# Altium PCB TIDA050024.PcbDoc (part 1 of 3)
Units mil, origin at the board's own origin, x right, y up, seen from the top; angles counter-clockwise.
Board outline 5500.19 x 3301.39 mil, 4 copper layers (Top Layer, Signal Layer 1, Signal Layer 2, Bottom Layer), stack 46.8 mil thick; 153 components, 88 nets, 368 pads, 374 vias.
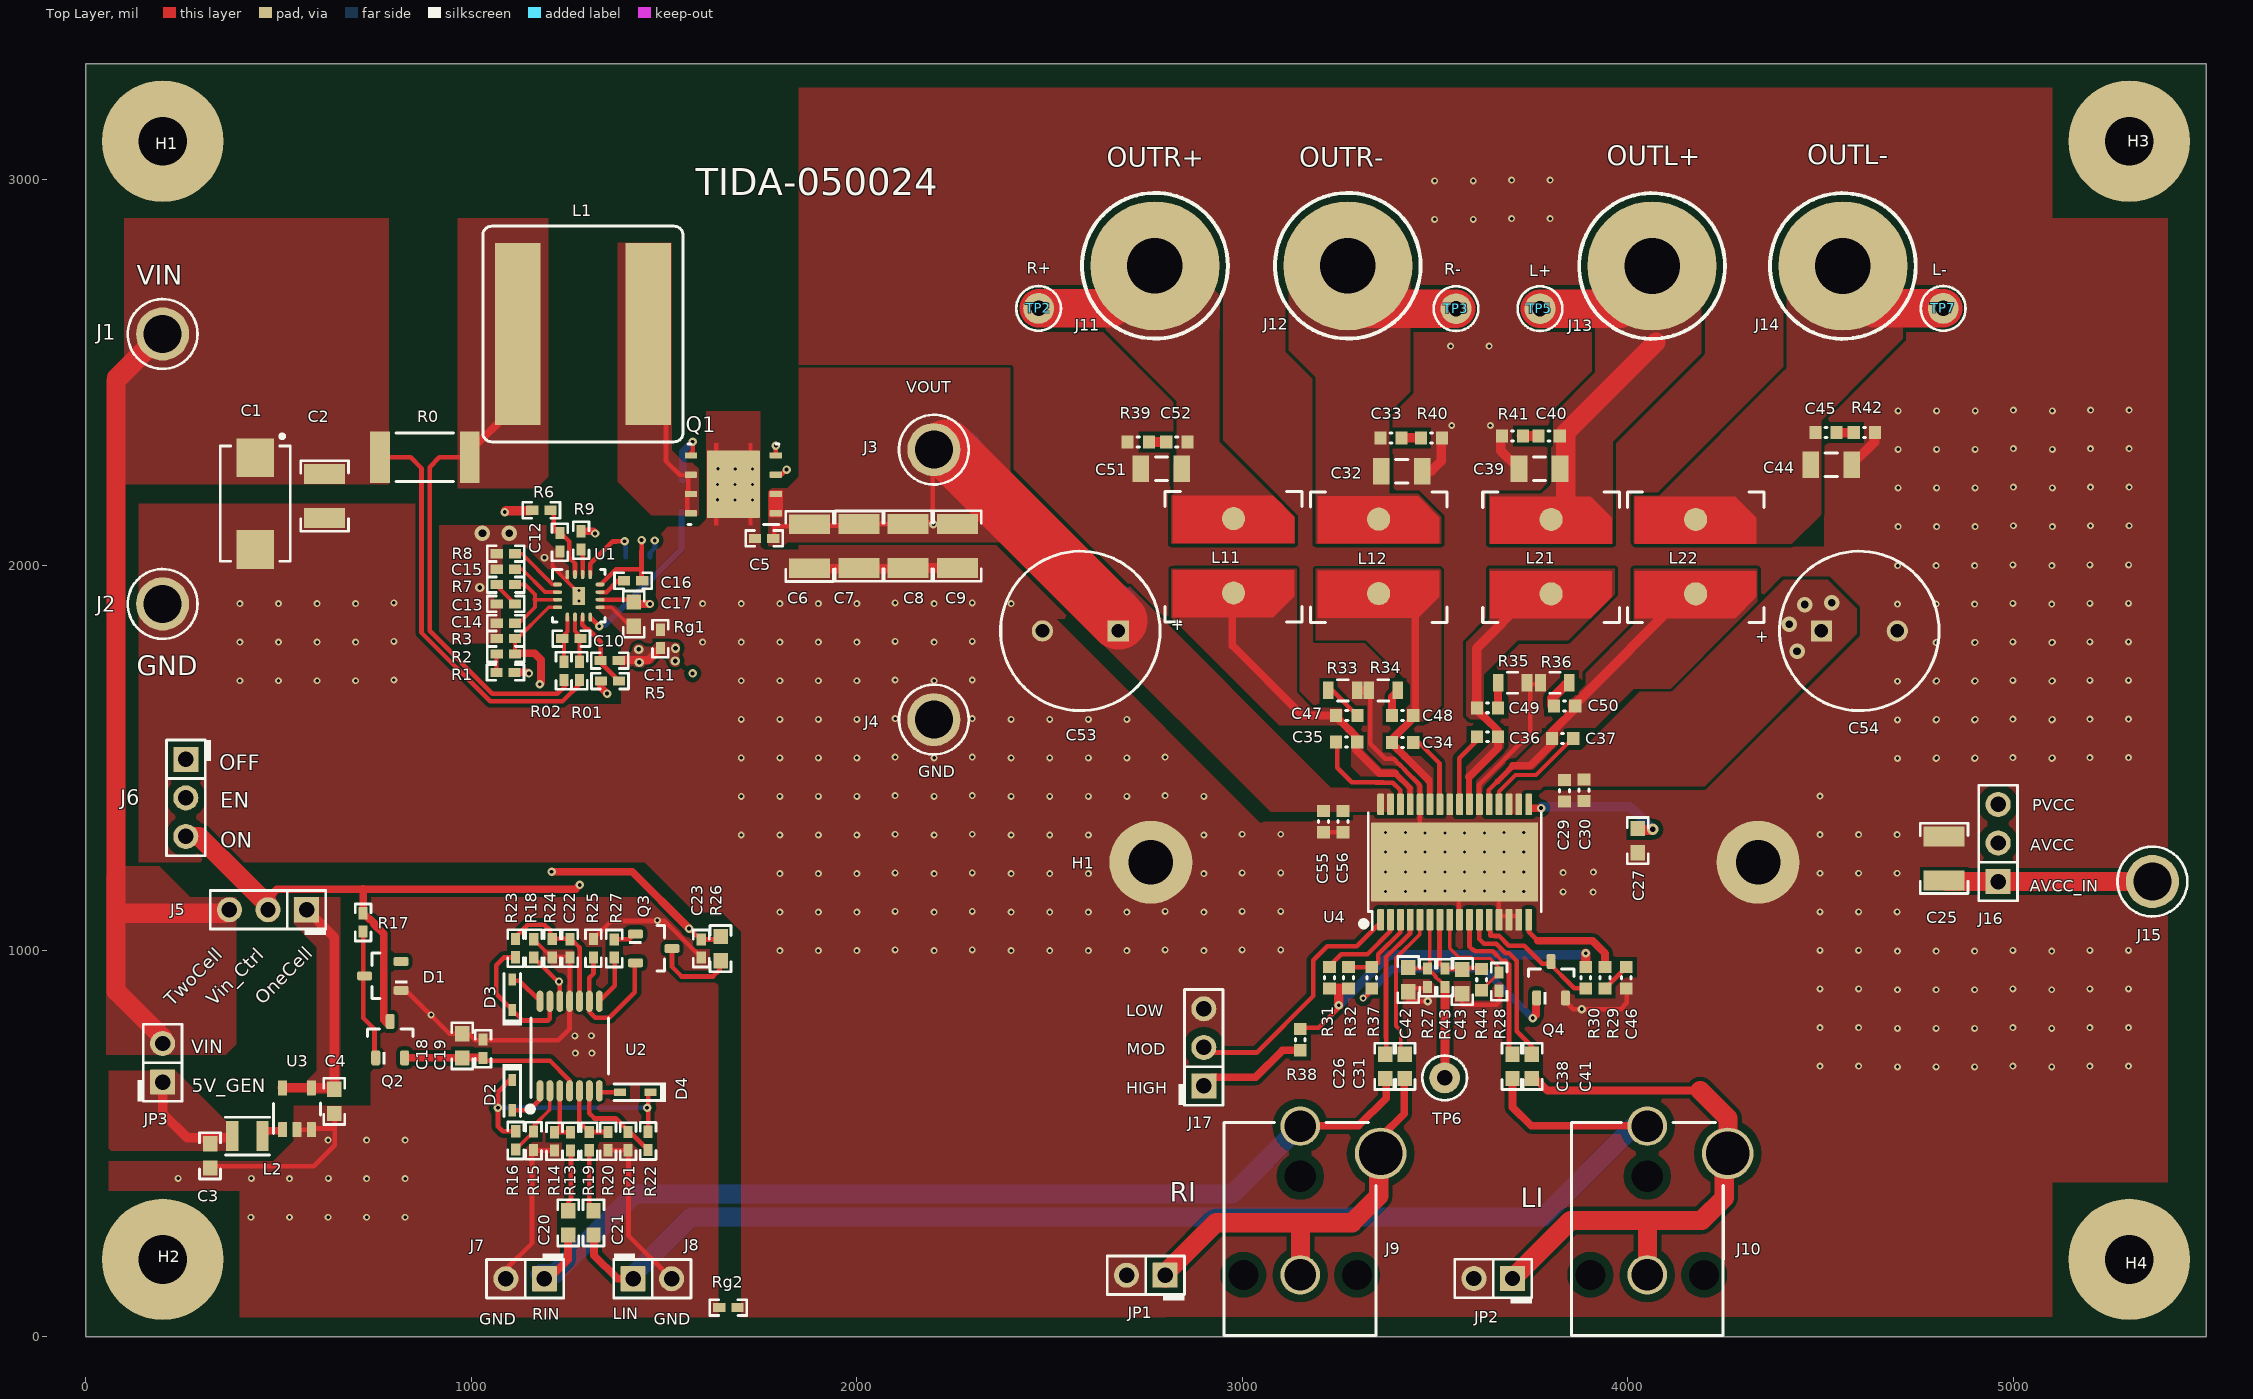
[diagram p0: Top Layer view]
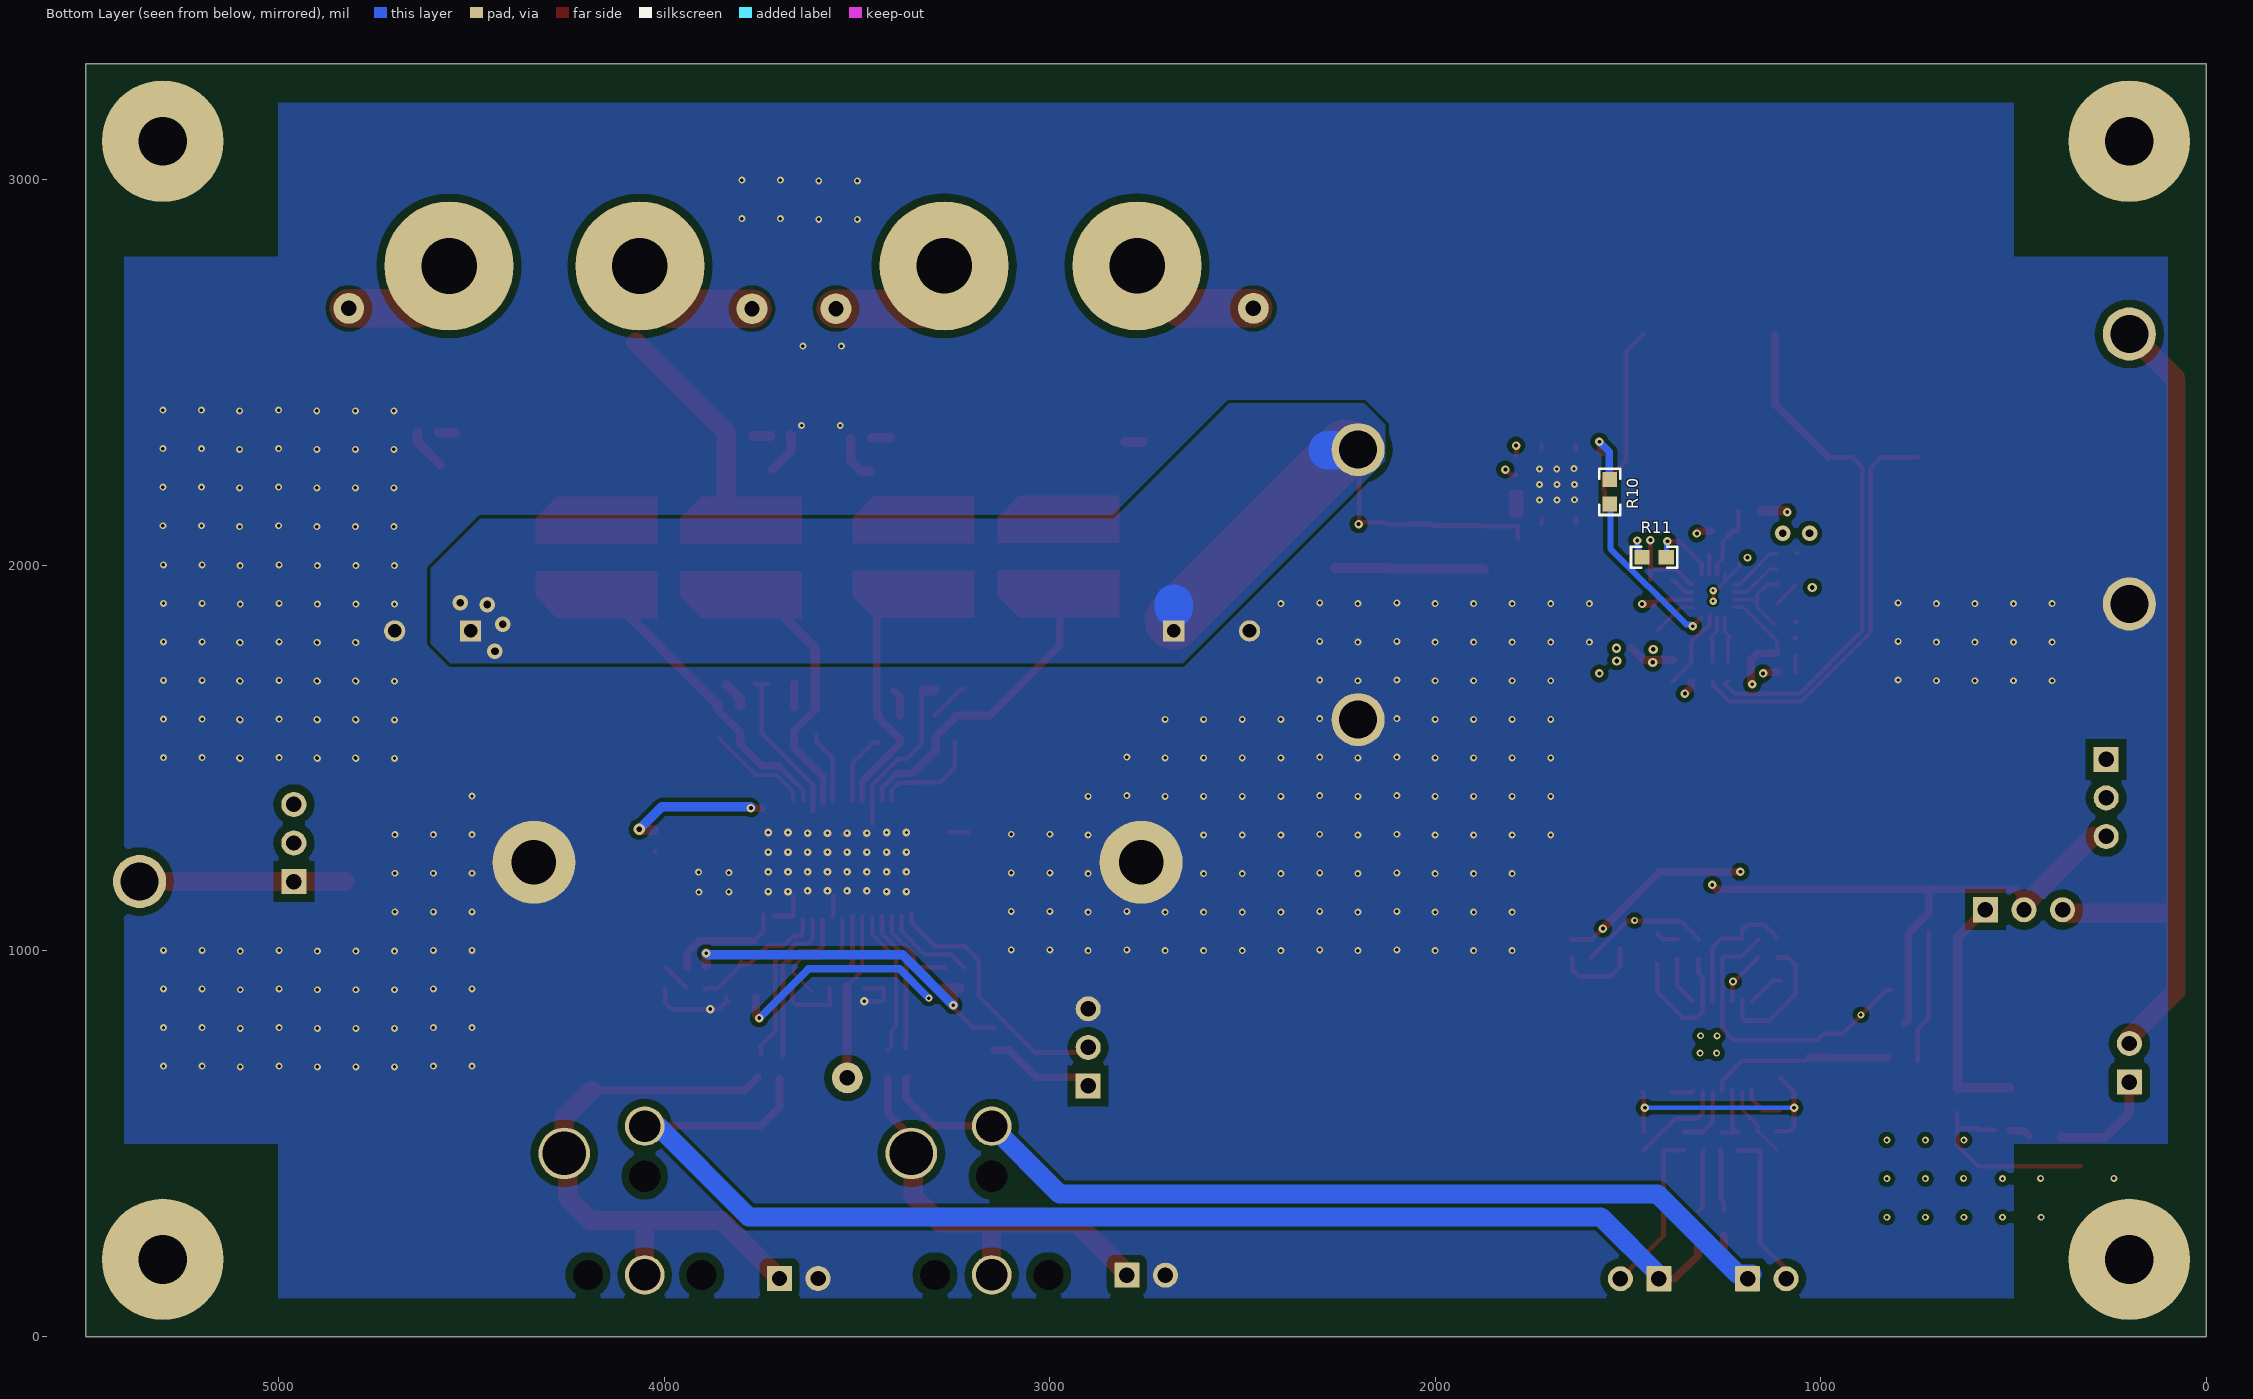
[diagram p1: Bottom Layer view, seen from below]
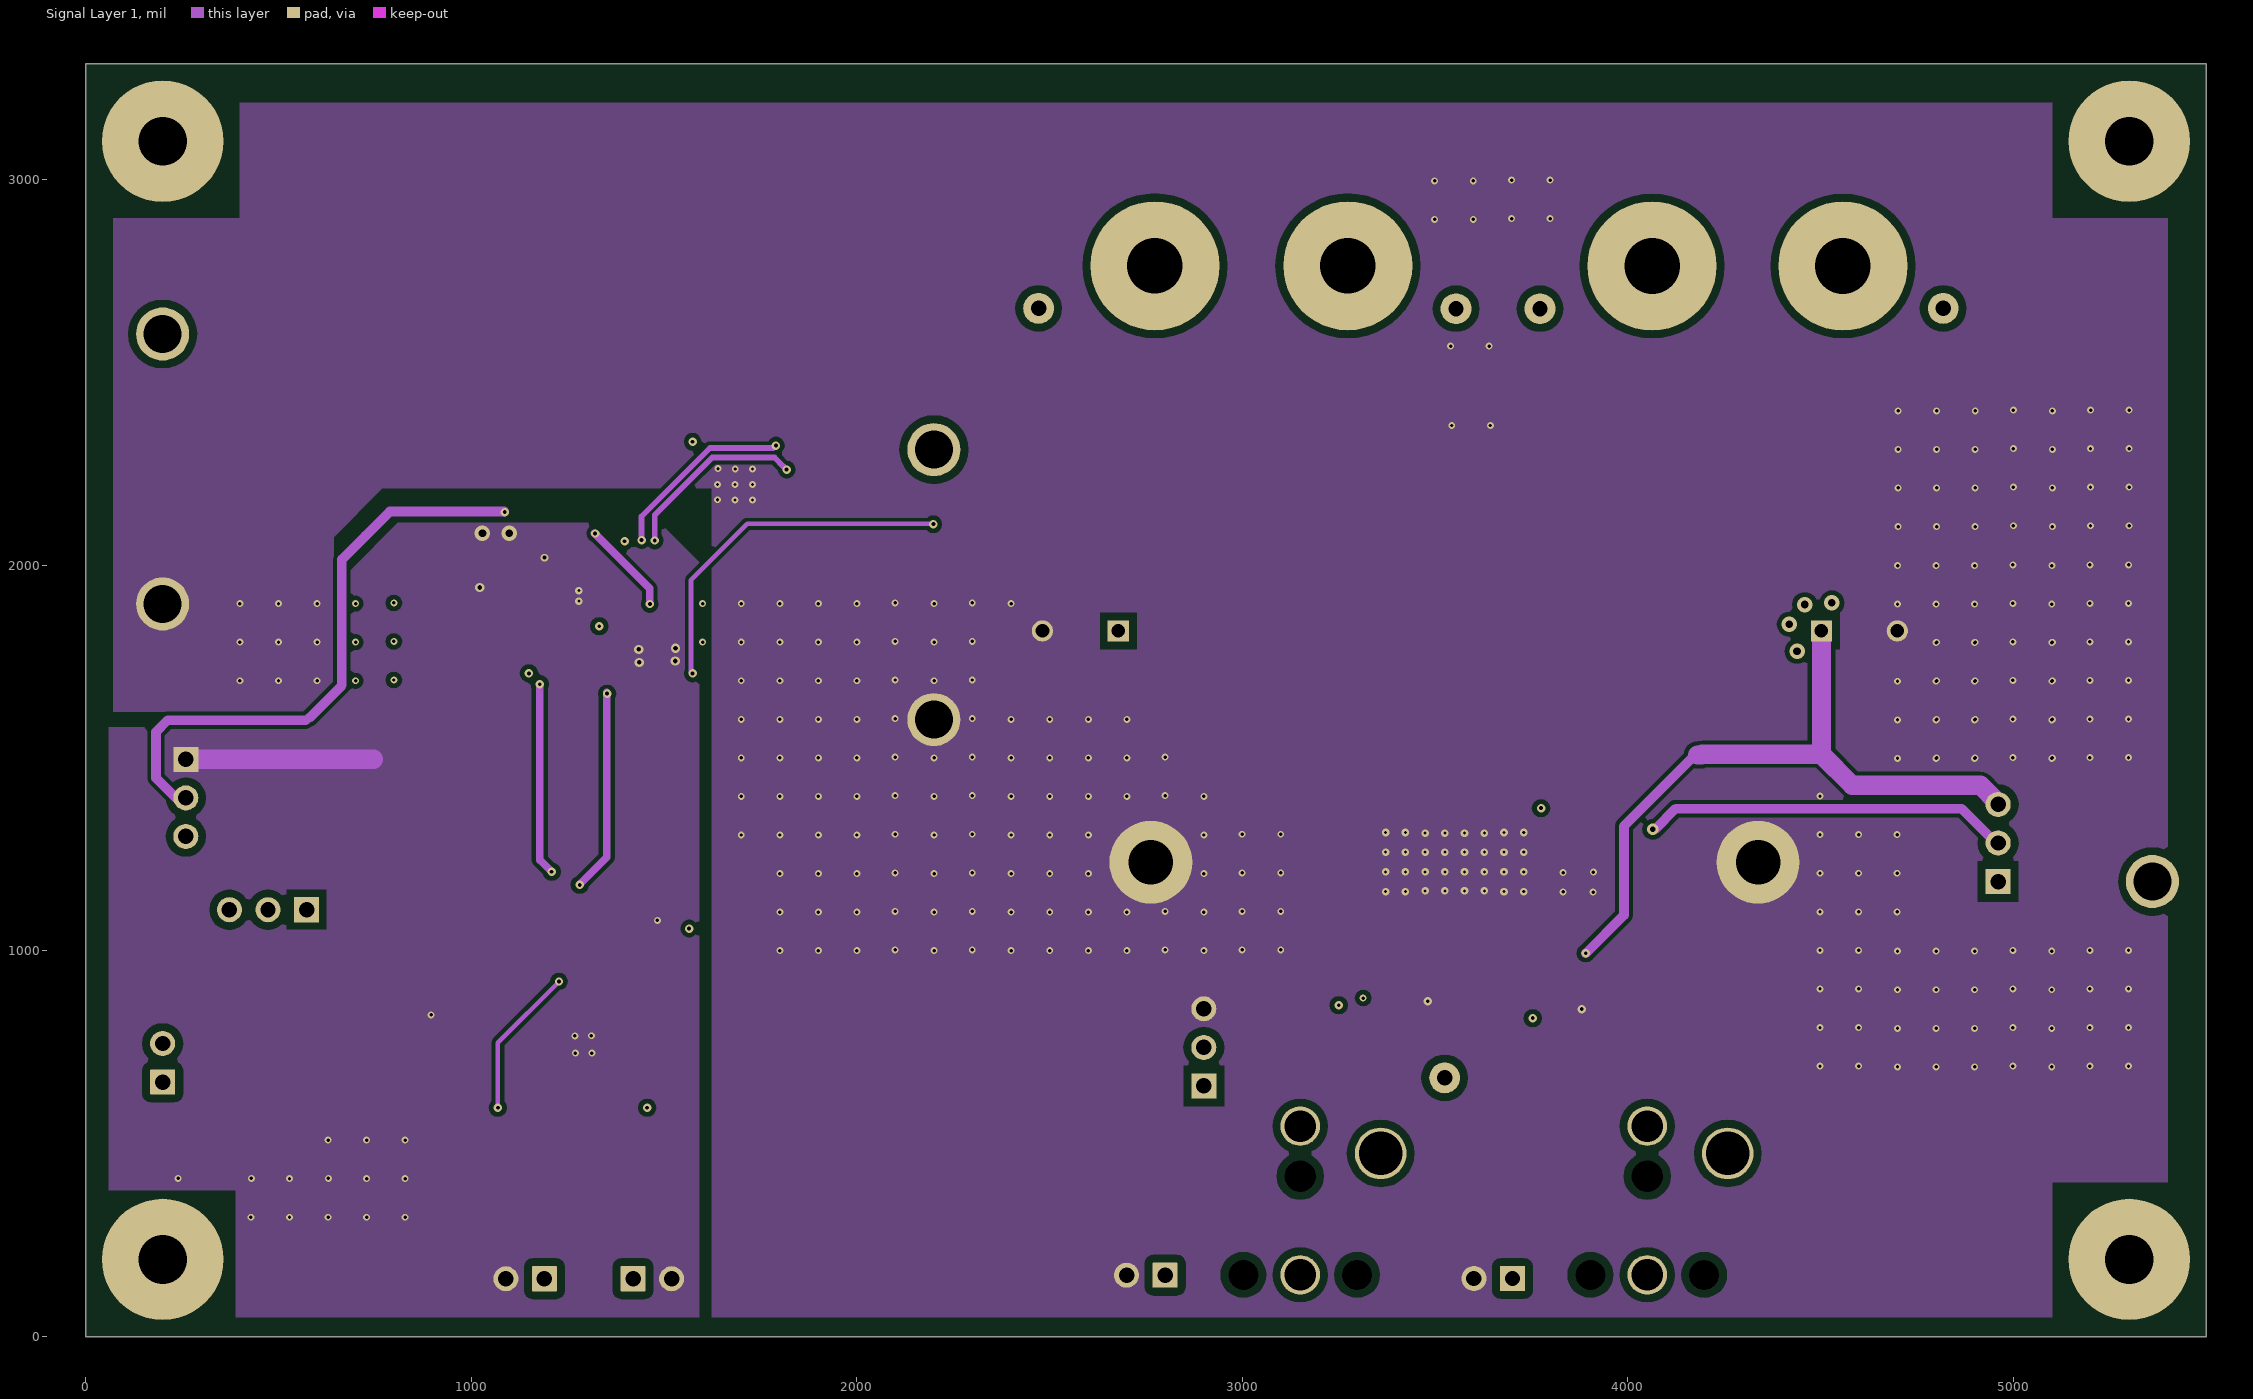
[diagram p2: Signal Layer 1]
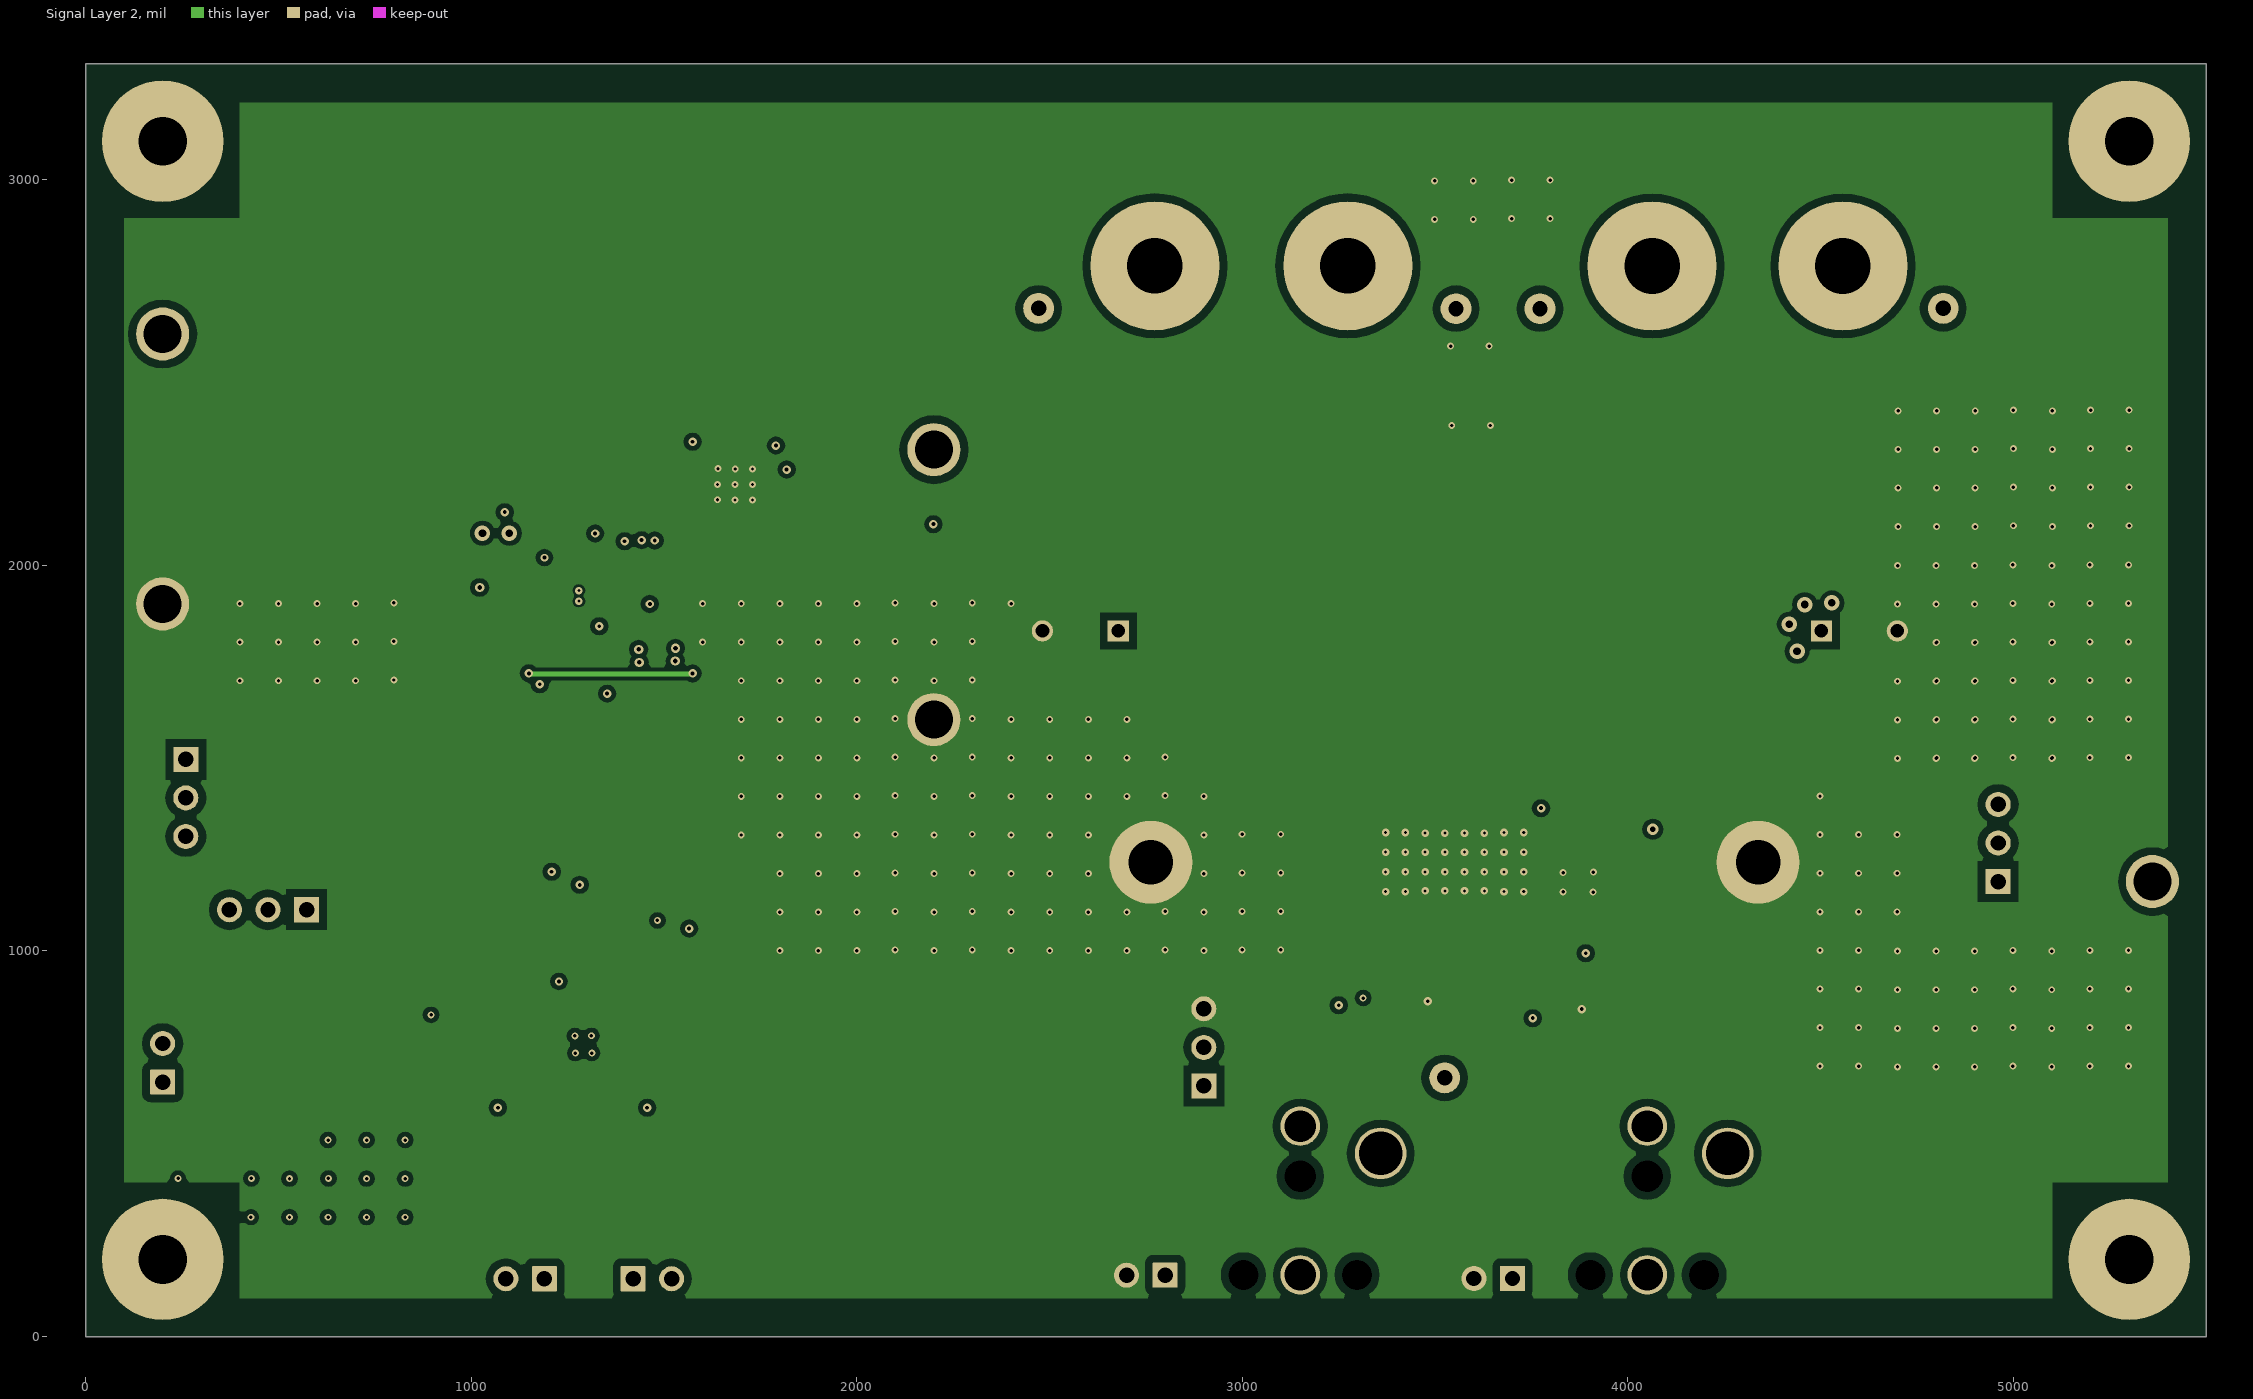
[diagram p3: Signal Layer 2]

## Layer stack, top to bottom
Top Solder: solder mask 0.4, Solder Resist, Dk 3.5
Top Layer: signal copper 2.8
Dielectric1: core 12.8, FR-4, Dk 4.2
Signal Layer 1: signal copper 1.4
Dielectric 3: core 12.8, Dk 4.2
Signal Layer 2: signal copper 1.4
Dielectric 2: core 12.8, Dk 4.2
Bottom Layer: signal copper 2.8
Bottom Solder: solder mask 0.4, Solder Resist, Dk 3.5

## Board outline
0,0 5500,0 5500.19,0.19 5500.19,3301.39 0.57,3301.39

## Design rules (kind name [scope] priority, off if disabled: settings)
AcuteAngle [All] p1: minimum=4.50000000000000E+0001 checktracksonly=FALSE
AssemblyTestPointUsage [All] p1: valid=2
Clearance "U1 Clearance" [InComponent('U1')] p1: gap=6 ignorepadtopadclearanceinfootprint=FALSE except(0: Arc-Hole Track-Hole SMDPad-Hole THPad-Hole Via-Hole Fill-Hole Poly-Hole Region-Hole Text-Hole)
Clearance "U2 Clearance" [InComponent('U2')] p2: gap=7.5 ignorepadtopadclearanceinfootprint=FALSE except(0: Arc-Hole Track-Hole SMDPad-Hole THPad-Hole Via-Hole Fill-Hole Poly-Hole Region-Hole Text-Hole; 7: Arc-Text)
Clearance "U3 Clearance" [InComponent('U3')] p3: gap=7.5 ignorepadtopadclearanceinfootprint=FALSE except(0: Arc-Hole Track-Hole SMDPad-Hole THPad-Hole Via-Hole Fill-Hole Poly-Hole Region-Hole Text-Hole; 7: Arc-Text)
Clearance Clearance_BoardEdge [OnCopper and Not InComponentClass('Logo') and not InComponentClass('FiducialMark') and not InRegion(1000,500,4000,800) vs IsKeepOut] p4: gap=15 ignorepadtopadclearanceinfootprint=FALSE except(0: Arc-Hole Track-Region Track-Hole SMDPad-Hole THPad-Hole Via-Hole Fill-Hole Poly-Hole Region-Hole Text-Hole; 10: Track-Poly Poly-Poly Poly-Region Poly-Text Region-Region Region-Text; 30: Arc-Arc Text-Text)
Clearance [All] p5: gap=8 ignorepadtopadclearanceinfootprint=FALSE except(0: Arc-Hole Track-Hole SMDPad-Hole THPad-Hole Via-Hole Fill-Hole Poly-Hole Region-Hole Text-Hole; 6: Track-Track Track-SMDPad SMDPad-SMDPad SMDPad-THPad; 10: Track-Poly SMDPad-Poly; 12: Via-Poly; 20: THPad-Poly)
ComponentClearance ComponentClearance_MountingHoles_FiducialMarks [InComponentClass('Mounting Holes') vs InComponentClass('FiducialMark')] p1: gap=20 collisioncheckmode=3 verticalgap=10 showdistances=FALSE
ComponentClearance ComponentClearance_SHUNT [InComponentClass('Shunt')] p2: gap=0 collisioncheckmode=3 verticalgap=0 showdistances=FALSE
ComponentClearance ComponentClearance_Logo [All] p3: gap=10 collisioncheckmode=3 verticalgap=10 showdistances=FALSE
ComponentClearance ComponentClearance_ScrewToNut [(HasFootprint('NY PMS 440 0025 PH')) vs (HasFootprint('Keystone_1902C'))] p4: gap=5 collisioncheckmode=3 verticalgap=10 showdistances=FALSE
ComponentClearance ComponentClearance_MountingHoles [InComponentClass('Mounting Holes')] p5: gap=250 collisioncheckmode=3 verticalgap=100000 showdistances=FALSE
ComponentClearance ComponentClearance_SmallPassives [HasFootprint('0201*') or HasFootprint('0402*') or HasFootprint('0508') or HasFootprint('0603*') or HasFootprint('0612') or HasFootprint('0805*') or HasFootprint('0815*') or HasFootprint('0830*') or HasFootprint('1206*') or HasFootprint('1210*') or HasFootprint('1808*') or HasFootprint('1812*') or HasFootprint('1825*') or HasFootprint('2010*') or HasFootprint('2220*') or HasFootprint('2225*') or HasFootprint('2512*') or HasFootprint('2728*') or HasFootprint('3518*') vs HasFootprint('0201*') or HasFootprint('0402*') or HasFootprint('0508') or HasFootprint('0603*') or HasFootprint('0612') or HasFootprint('0805*') or HasFootprint('0815*') or HasFootprint('0830*') or HasFootprint('1206*') or HasFootprint('1210*') or HasFootprint('1808*') or HasFootprint('1812*') or HasFootprint('1825*') or HasFootprint('2010*') or HasFootprint('2220*') or HasFootprint('2225*') or HasFootprint('2512*') or HasFootprint('2728*') or HasFootprint('3518*')] p6: gap=20 collisioncheckmode=3 verticalgap=10 showdistances=FALSE
ComponentClearance ComponentClearance_THtoSMT [IsThruComponent vs IsSMTComponent] p7 off: gap=10 collisioncheckmode=3 verticalgap=100000 showdistances=FALSE
ComponentClearance ComponentClearance_THtoTH [IsThruComponent vs IsThruComponent] p8: gap=10.11 collisioncheckmode=3 verticalgap=100000 showdistances=FALSE
ComponentClearance [All] p9: gap=10 collisioncheckmode=3 verticalgap=10 showdistances=FALSE
DiffPairsRouting [All] p1: maxlimit=100 minlimit=10 mostfreqgap=10 toplayer_minwidth=15 toplayer_maxwidth=15 toplayer_prefwidth=15 midlayer1_minwidth=15 midlayer1_maxwidth=15 midlayer1_prefwidth=15 midlayer2_minwidth=15 midlayer2_maxwidth=15 midlayer2_prefwidth=15 bottomlayer_minwidth=15 bottomlayer_maxwidth=15 bottomlayer_prefwidth=15 maxuncoupledlength=1000
FabricationTestPointUsage TestPointUsage [All] p1: valid=2 allowmultiple=FALSE
FabricationTestpoint Testpoint [All] p1: side=3 testpointundercomponent=TRUE minsize=40 maxsize=100 preferedsize=60 minholesize=0 maxholesize=40 preferedholesize=32 testpointgrid=1 allowsidetop=TRUE allowsidebottom=TRUE usegrid=TRUE gridtolerance=0.01
FanoutControl Fanout_LCC [IsLCC] p1: bgadir=Out bgaviamode=Centered fanoutstyle=Auto fanoutdirection=Alternating viagrid=1 // Fanout_LCC (Default Rule)
FanoutControl Fanout_BGA [IsBGA] p2: bgadir=Out bgaviamode=Centered fanoutstyle=Auto fanoutdirection=Alternating viagrid=1 // Fanout_BGA (Default Rule)
FanoutControl Fanout_Default [All] p4: bgadir=Out bgaviamode=Centered fanoutstyle=Auto fanoutdirection=Alternating viagrid=1 // Fanout_Default (Default Rule)
FanoutControl Fanout_Small [(CompPinCount < 5)] p5: bgadir=Out bgaviamode=Centered fanoutstyle=Auto fanoutdirection=OutThenIn viagrid=1 // Fanout_Small (Default Rule)
HoleSize [All] p1: absolutevalues=TRUE maxlimit=100 minlimit=8 maxpercent=80.000 minpercent=20.000
HoleToHoleClearance [All] p1: gap=1 allowstackedmicrovias=TRUE
MinimumAnnularRing MinimumAnnularRing_small [TouchesRoom('BGA_Room')] p1: minimumring=2.8
MinimumAnnularRing MinimumAnnularRing_ThermalPadVias [IsVia and InAnyComponent] p2: minimumring=5.91
MinimumAnnularRing [All] p3: minimumring=5
MinimumSolderMaskSliver MinimumSolderMaskSliver_Logo [InComponentClass('Logo') vs InComponentClass('Logo')] p1: minsoldermaskwidth=0.7
MinimumSolderMaskSliver [All] p2: minsoldermaskwidth=3
PlaneClearance [All] p1: clearance=10
PlaneConnect [All] p1: planeconnectstyle=Direct reliefexpansion=10 reliefentries=4 reliefconductorwidth=10 reliefairgap=10
PolygonConnect PolygonConnect-TH-Relief [IsPoly vs (IsThruPin)  And Not (InComponent('U3'))  And Not (InComponent('U4'))] p1: connectstyle=Direct reliefconductorwidth=20 reliefentries=4 polygonreliefangle="90 Angle" airgapwidth=10
PolygonConnect PolygonConnect-DirectConn [All] p2: connectstyle=Direct reliefconductorwidth=10 reliefentries=4 polygonreliefangle="90 Angle" airgapwidth=10
PolygonConnect [All] p3: connectstyle=Relief reliefconductorwidth=10 reliefentries=4 polygonreliefangle="90 Angle" airgapwidth=10
RoutingVias ThermalPadVias [IsVia and InAnyComponent] p1: holewidth=7.87 width=19.68 viastyle="Through Hole" minholewidth=7.87 minwidth=19.68 maxholewidth=12.99 maxwidth=23.62
RoutingVias [All] p2: holewidth=10 width=22 viastyle="Through Hole" minholewidth=4 minwidth=10 maxholewidth=100 maxwidth=100
SMDToCorner [All] p1: distance=0
SilkToBoardRegionClearance [Not ((IsComment or IsDesignator) And (Hide <> 'False')) and not InRegion(1000,500,4000,800)] p1:
SilkToSilkClearance SilkToSilkClearance_Pb-FreeLogo [(HasFootprint('Pb-Free_Overlay_Medium') OR HasFootprint('Pb-Free_Overlay_Small')) vs (HasFootprint('Pb-Free_Overlay_Medium') OR HasFootprint('Pb-Free_Overlay_Small'))] p1: silktosilkclearance=0
SilkToSilkClearance [All] p2: silktosilkclearance=3
SilkToSolderMaskClearance SilkToComonentPadClearance [IsPad and InAnycomponent] p1 off: minsilkscreentomaskgap=5 clearancetoexposedcopper=TRUE
SilkToSolderMaskClearance "Silk to Solder Mask Opening" [All] p2 off: minsilkscreentomaskgap=4 clearancetoexposedcopper=TRUE
SolderMaskExpansion [All] p1: expansion=1
Width [All] p1: maxlimit=100 minlimit=6 preferedwidth=10 checkconnectedcopper=TRUE
13 further rules are at their usual default settings.

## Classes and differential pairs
component class "Mounting Holes": H1 H2 H3 H4
component class AssemblyNote: ZZ1 ZZ2 ZZ3
component class TIDA050024_Hardware: H1 H2 H3 H4 ZZ1 ZZ2 ZZ3
component class TIDA050024_1: C1 C2 C3 C4 C5 C6 C7 C8 C9 C10 C11 C12 C13 C14 C15 C16 C17 C18 C19 C20 C21 C22 C23 D1 D2 D3 D4 J1 J2 J3 J4 J5 J6 J7 J8 JP3 L1 L2 Q1 Q2 Q3 R0 R1 R01 R02 R2 R3 R5 R6 R7 R8 R9 R10 R11 R12 R13 R14 R15 R16 R17 R18 R19 R20 R21 R22 R23 R24 R25 R26 R27 Rg1 Rg2 U1 U2 U3
component class Header: J5 J6 J7 J8 J16 J17 JP1 JP2 JP3
component class "Full Flood": C29 C30 C34 C35 C36 C37 C55 C56 R33 R34 R35 R36
component class "LC Caps": C32 C39 C44 C51
component class TIDA050024_2: C25 C26 C27 C29 C30 C31 C32 C33 C34 C35 C36 C37 C38 C39 C40 C41 C42 C43 C44 C45 C46 C47 C48 C49 C50 C51 C52 C53 C54 C55 C56 H1 J9 J10 J11 J12 J13 J14 J15 J16 J17 JP1 JP2 L11 L12 L21 L22 Q4 R27 R28 R29 R30 R31 R32 R33 R34 R35 R36 R37 R38 R39 R40 R41 R42 R43 R44 TP2 TP3 TP5 TP6 TP7 U4

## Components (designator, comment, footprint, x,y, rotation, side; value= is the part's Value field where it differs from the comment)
C1 "T495D476M025ATE120" 7343-31 440,2160 r270 top value=47uF
C2 "GRM32ER61E226KE15L" 1210_270 620,2180 r270 top value=22uF
C3 "GRM188R61E106MA73D" 0603 322.91,468.45 r270 top value=10uF
C4 "GRM188R61E106MA73D" 0603 645,610 r270 top value=10uF
C5 "C1005X5R1E105K050BC" 0402 1760,2070 r180 top value=1uF
C6 "GRM32ER61E226KE15L" 1210_270 1877.87,2049.47 r270 top value=22uF
C7 "GRM32ER61E226KE15L" 1210_270 2005.85,2049.96 r270 top value=22uF
C8 "GRM32ER61E226KE15L" 1210_270 2133.02,2050.19 r270 top value=22uF
C9 "GRM32ER61E226KE15L" 1210_270 2260.76,2050.18 r270 top value=22uF
C10 "GRM1555C1H101JA01D" 0402 1260,1810 r0 top value=100pF
C11 "CGA2B3X7R1H104K050BB" 0402 1359.34,1752.85 r0 top value=0.1uF
C12 "CGA2B3X7R1H104K050BB" 0402 1230,2060 r270 top value=0.1uF
C13 "GCM155R71E223KA55D" 0402 1090,1900 r180 top value=0.022uF
C14 "GRM1555C1H101JA01D" 0402 1090,1850 r180 top value=100pF
C15 "CGA2B3X7R1H104K050BB" 0402 1090,1990 r180 top value=0.1uF
C16 "CGA2B3X7R1H104K050BB" 0402 1420,1960 r180 top value=0.1uF
C17 "GRM188R61E106MA73D" 0603 1421.37,1873.58 r270 top value=10uF
C18 "GRM188R61E106MA73D" 0603 976.99,754.04 r90 top value=10uF
C19 "CGA2B3X7R1H104K050BB" 0402 1031,746.41 r90 top value=0.1uF
C20 "GRM188R61E106MA73D" 0603 1251.93,295.02 r90 top value=10uF
C21 "GRM188R61E106MA73D" 0603 1317.29,294.67 r90 top value=10uF
C22 "C1005X5R1E105K050BC" 0402 1256.12,1006.77 r270 top value=1uF
C23 "GRM1555C1H101JA01D" 0402 1596.87,1006.26 r270 top value=100pF
C25 "GRM32ER61E226KE15L" 1210_270 4820,1240 r90 top value=22uF
C26 "GRM188R61E105KA12D" 0603 3370.57,700.57 r90 top value=1uF
C27 "GRM188R61E105KA12D" 0603 4025.43,1286.03 r270 top value=1uF
C29 "GCM188R71H104KA57D" 0603L 3835.57,1415.57 r90 top value=0.1uF
C30 "GRM1885C1H102JA01D" 0603L 3886.18,1416.92 r90 top value=1000pF
C31 "GRM188R61E105KA12D" 0603 3420.57,700.57 r90 top value=1uF
C32 "GRM31MR71H684KA88L" 1206L 3413.43,2244.29 r0 top value=0.68uF
C33 "GRM188R71H103KA01D" 0603L 3385.57,2330.57 r0 top value=0.01uF
C34 "GCM188R71H104KA57D" 0603L 3415.57,1540.57 r0 top value=0.1uF
C35 "GCM188R71H104KA57D" 0603L 3270.23,1542.04 r180 top value=0.1uF
C36 "GCM188R71H104KA57D" 0603L 3635.57,1555.57 r180 top value=0.1uF
C37 "GCM188R71H104KA57D" 0603L 3830.57,1550.57 r0 top value=0.1uF
C38 "GRM188R61E105KA12D" 0603 3700.57,700.57 r90 top value=1uF
C39 "GRM31MR71H684KA88L" 1206L 3770.57,2250.57 r180 top value=0.68uF
C40 "GRM188R71H103KA01D" 0603L 3795.57,2335.57 r180 top value=0.01uF
C41 "GRM188R61E105KA12D" 0603 3750.57,700.57 r90 top value=1uF
C42 "GRM188R61E105KA12D" 0603 3430.57,925.57 r90 top value=1uF
C43 "GRM188R61E105KA12D" 0603 3570.57,920.57 r90 top value=1uF
C44 "GRM31MR71H684KA88L" 1206L 4527.15,2260.95 r0 top value=0.68uF
C45 "GRM188R71H103KA01D" 0603L 4513.48,2344.34 r0 top value=0.01uF
C46 "GRM1885C1H470JA01D" 0603L 3995.57,930.57 r270 top value=47pF
C47 "GRM1885C1H331JA01D" 0603L 3270.57,1610.57 r180 top value=330pF
C48 "GRM1885C1H331JA01D" 0603L 3415.57,1610.57 r0 top value=330pF
C49 "GRM1885C1H331JA01D" 0603L 3635.57,1630.57 r180 top value=330pF
C50 "GRM1885C1H331JA01D" 0603L 3835.57,1635.57 r0 top value=330pF
C51 "GRM31MR71H684KA88L" 1206L 2790,2250 r180 top value=0.68uF
C52 "GRM188R71H103KA01D" 0603L 2830,2320 r180 top value=0.01uF
C53 "EEU-FC1V221" FC_1000x1250 2580,1830 r180 top value=220uF
C54 "EEU-FC1V221" FC_1000x1250 4600,1830 r0 top value=220uF
C55 "GCM188R71H104KA57D" 0603L 3210.57,1335.57 r90 top value=0.1uF
C56 "GRM1885C1H102JA01D" 0603L 3260.57,1335.57 r90 top value=1000pF
D1 "BZX84C4V3LT1G" SOT-23 770.87,935.34 r180 top value=4.3V
D2 "1N4148WT" Fairchild_SOD-523F 1106.87,626.26 r270 top value=75V
D3 "1N4148WT" Fairchild_SOD-523F 1106.87,886.26 r90 top value=75V
D4 "1N4148WT" Fairchild_SOD-523F 1425.49,633.82 r180 top value=75V
H1 "NY PMS 440 0025 PH" "NY PMS 440 0025 PH" 200,3100 r90 top
H1 "ATS-TI10P-521-C1-R1" HSINK_ATS-TI10P-521-C1-R1 3550,1230 r180 top locked
H2 "NY PMS 440 0025 PH" "NY PMS 440 0025 PH" 200,200 r90 top
H3 "NY PMS 440 0025 PH" "NY PMS 440 0025 PH" 5300,3100 r90 top
H4 "NY PMS 440 0025 PH" "NY PMS 440 0025 PH" 5300,200 r90 top
J1 "1502-2" Keystone1502-2 200,2600 r0 top
J2 "1502-2" Keystone1502-2 200,1900 r0 top
J3 "1502-2" Keystone1502-2 2200,2300 r0 top
J4 "1502-2" Keystone1502-2 2200,1600 r0 top
J5 "TSW-103-07-G-S" TSW-103-07-G-S 473.18,1106.94 r180 top
J6 "TSW-103-07-G-S" TSW-103-07-G-S 260.09,1397.08 r270 top
J7 "TSW-102-07-G-S" TSW-102-07-G-S 1140,150 r180 top
J8 "TSW-102-07-G-S" TSW-102-07-G-S 1470,150 r0 top
J9 "RIN" Keystone_971 3150,160 r90 top
J10 "LIN" Keystone_970 4050,160 r90 top
J11 "ROUT+" Keystone_7006 2773.39,2776.89 r0 top
J12 "ROUT-" Keystone_7007 3273.39,2776.89 r0 top
J13 "LOUT+" Keystone_7006 4062.44,2776.3 r0 top
J14 "LOUT-" Keystone_7007 4557.44,2776.3 r0 top
J15 "Suggest using a net name here" Keystone1502-2 5360,1180 r0 top value=Double
J16 "AVCC-SEL" PBC03SAAN 4960,1280 r90 top
J17 "TSW-103-07-G-S" TSW-103-07-G-S 2900,750 r90 top
JP1 "TSW-102-07-G-S" TSW-102-07-G-S 2749.79,159.14 r180 top
JP2 "TSW-102-07-G-S" TSW-102-07-G-S 3650.57,150.57 r180 top
JP3 "TSW-102-07-G-S" TSW-102-07-G-S 200,710 r90 top
L1 "XAL1350-302MEB" XAL1350 1290,2600 r0 top value=3uH
L2 "DFE252012F-2R2M=P2" DFE252012C 420,520 r0 top value=2.2uH
L11 "SRT8045-103MEB" SRT8045 2977.09,2022.82 r90 top value=10uH
L12 "SRT8045-103MEB" SRT8045 3353.47,2021.36 r90 top value=10uH
L21 "SRT8045-103MEB" SRT8045 3800.57,2020.57 r90 top value=10uH
L22 "SRT8045-103MEB" SRT8045 4175.57,2020.57 r90 top value=10uH
Q1 "CSD87351Q5D" DQY0008A 1680,2210 r180 top value=30V
Q2 "BC850CLT1G" SOT-23 790,770 r90 top value="45 V"
Q3 "BSS138" SOT-23 1473.54,1006.62 r0 top value=50V
Q4 "BC850CLT1G" SOT-23 3800.57,925.57 r90 top value="45 V"
R0 "CSNL2512FT2L00" 2512 880,2280 r0 top value=0.002
R01 "CRCW040210R0FKED" 0402 1280.56,1726.59 r270 top value=10.0
R1 "CRCW040249R9FKED" 0402 1089.01,1722.61 r0 top value=49.9
R02 "CRCW040210R0FKED" 0402 1240.56,1726.59 r270 top value=10.0
R2 "ERJ-2RKF2003X" 0402 1090,1770 r180 top value=200k
R3 "CRCW040256K2FKED" 0402 1090,1810 r0 top value=56.2k
R5 "CRCW040210R0FKED" 0402 1360,1700 r180 top value=10.0
R6 "CRCW040210R0FKED" 0402 1182.18,2142.81 r180 top value=10.0
R7 "CRCW04027K50FKED" 0402 1090,1950 r0 top value=7.50k
R8 "CRCW0402137KFKED" 0402 1090,2030 r0 top value=137k
R9 "CRCW0402100KFKED" 0402 1285,2065 r270 top value=100k
R10 "RCS06030000Z0EA" 0603 1547.78,2190.77 r90 bottom value=0
R11 "RCS06030000Z0EA" 0603 1432.37,2021.02 r0 bottom value=0
R13 "CRCW04020000Z0ED" 0402 1257.9,506.32 r270 top value=0
R14 "CRCW0402100KDHEDP" 0402 1215.81,506.32 r90 top value=100k
R15 "CRCW040210K2FKED" 0402 1162.1,507.78 r90 top value=10.2k
R16 "CRCW040210K2FKED" 0402 1115.71,508.72 r90 top value=10.2k
R17 "CRCW04023K01FKED" 0402 720.03,1074.02 r90 top value=3.01k
R18 "CRCW0402100KDHEDP" 0402 1162.44,1006.77 r270 top value=100k
R19 "CRCW04020000Z0ED" 0402 1306.42,506.7 r270 top value=0
R20 "CRCW0402100KDHEDP" 0402 1355.33,506.82 r90 top value=100k
R21 "CRCW040210K2FKED" 0402 1407.1,506.82 r90 top value=10.2k
R22 "CRCW040210K2FKED" 0402 1459.04,507.43 r90 top value=10.2k
R23 "CRCW040212R1FKED" 0402 1115.13,1007.4 r90 top value=12.1
R24 "ERJ-2RKF1004X" 0402 1210.39,1007.09 r90 top value=1.00Meg
R25 "CRCW040218K7FKED" 0402 1317.3,1006.97 r270 top value=18.7k
R26 "CRCW060310K5FKEA" 0603 1646.87,1006.26 r90 top value=10.5k
R27 "CRCW04020000Z0ED" 0402 1371.04,1006.51 r270 top value=0
R27 "CRCW040220K5FKED" 0402 3480.57,930.57 r90 top value=20.5k
R28 "CRCW040239K0JNED" 0402 3665.57,920.57 r90 top value=39k
R29 "RG1608P-472-B-T5" 0603L 3940.57,930.57 r90 top value=4.70k
R30 "RC0603FR-07100KL" 0603L 3890.57,930.57 r270 top value=100k
R31 "RC0603FR-07499KL" 0603L 3225.57,930.57 r270 top value=499k
R32 "RC0603FR-07100KL" 0603L 3275.57,930.57 r90 top value=100k
R33 "CRCW080510R0JNEA" 0805_KTR 3260.57,1675.57 r180 top value=10
R34 "CRCW080510R0JNEA" 0805_KTR 3365.57,1675.57 r0 top value=10
R35 "CRCW080510R0JNEA" 0805_KTR 3700.57,1695.57 r180 top value=10
R36 "CRCW080510R0JNEA" 0805_KTR 3810.57,1695.57 r0 top value=10
R37 "RC0603FR-07100KL" 0603L 3335.57,930.57 r270 top value=100k
R38 "RC0603FR-07100KL" 0603L 3150,770 r90 top value=100k
R39 "CRCW06033R30JNEA" 0603L 2730,2320 r0 top value=3.3
R40 "CRCW06033R30JNEA" 0603L 3490.57,2330.57 r180 top value=3.3
R41 "CRCW06033R30JNEA" 0603L 3700.57,2335.57 r0 top value=3.3
R42 "CRCW06033R30JNEA" 0603L 4613.14,2344.93 r180 top value=3.3
R43 "ERJ-2GE0R00X" 0402 3525.57,930.57 r90 top value=0
R44 "RC0603FR-07100KL" 0603L 3620.57,925.57 r270 top value=100k
Rg1 "CRCW04020000Z0ED" 0402 1490.91,1809.42 r90 top value=0
Rg2 "CRCW04020000Z0ED" 0402 1666.88,75.17 r0 top value=0
TP2 "R+" Keystone5003 2471.45,2666.3 r0 top value=Orange
TP3 "R-" Keystone5003 3554.07,2665.65 r0 top value=Orange
TP5 "L+" Keystone5003 3771.82,2665.65 r0 top value=Orange
TP6 "PLIMIT" Keystone5003 3524.6,670.85 r0 top value=Orange
TP7 "L-" Keystone5003 4817.44,2666.3 r0 top value=Orange
U1 "TPS43061RTER" RTE0016E 1279.16,1920.84 r0 top
U2 "OPA4377AIPW" PW0014A_N 1255.49,753.47 r90 top
U3 "TPS613222ADBVR" DBV0005A_N 548.26,590.78 r90 top
U4 "TPA3128D2DAPR" DAP0032A_N 3550.57,1230.57 r90 top locked
ZZ1 "These assemblies are ESD sensitive, ESD precautions shall be observed." AssemblyNote 185,3938 r0 top
ZZ2 "These assemblies must be clean and free from flux and all contaminants. Use of no clean flux is not acceptable." AssemblyNote 185,3829.11 r0 top
ZZ3 "These assemblies must comply with workmanship standards IPC-A-610 Class 2, unless otherwise specified." AssemblyNote 185,3740.56 r0 top

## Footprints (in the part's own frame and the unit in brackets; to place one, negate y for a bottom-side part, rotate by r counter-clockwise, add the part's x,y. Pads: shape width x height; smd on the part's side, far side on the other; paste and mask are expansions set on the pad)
0402 [mm] "0402 from SM-752 data"
  rect 0.8x0.6 smd: 1(-0.6,0) 2(0.6,0)
  silkscreen extent -1.22,-0.52 1.22,0.52, body extent -0.55,-0.3 0.55,0.3, height 0.6
0603 [mm] "0603 from SM-752 data"
  rect 1x0.95 smd: 1(-0.8,0) 2(0.8,0)
  silkscreen extent -1.52,-0.69 1.52,0.69, body extent -0.87,-0.47 0.87,0.47, height 1
0603L [mm] "0603 from SM-752 data"
  rect 0.8x0.85 smd: 1(-0.7,0) 2(0.7,0)
  silkscreen extent -0.07,-0.33 0.07,0.33, body extent -0.87,-0.47 0.87,0.47, height 1
0805_KTR [mm] "ROHM"
  rect 0.7x1.15 smd: 1(-0.95,0) 2(0.95,0)
  silkscreen extent -0.35,-0.7 0.35,0.7, body extent -1.05,-0.67 1.05,0.67, height 0.65
1206L [mm] "1206 from SM-752 data"
  rect 1.1x1.75 smd: 1(-1.35,0) 2(1.35,0)
  silkscreen extent -0.4,-0.77 0.4,0.77, body extent -1.7,-0.9 1.7,0.9, height 1.35
1210_270 [mm] "1210"
  rect 1.3x2.7 smd: 1(-1.45,0) 2(1.45,0)
  silkscreen extent -2.32,-1.57 2.32,1.57, body extent -1.7,-1.35 1.7,1.35, height 2.7
2512 [mm] "Chip Resistor, Body 6.3x3.2mm, IPC Medium Density"
  rect 1.3x3.4 smd: 1(-2.95,0) 2(2.95,0)
  silkscreen extent -1.9,-1.6 1.9,1.6, body extent -3.22,-1.67 3.22,1.67, height 0.71
7343-31 [mm] "Medium Density based on Kemet T495 dimensions"
  rect 2.55x2.45 smd: 1(-3.025,0) 2(3.025,0)
  silkscreen extent -4.56,-2.3 3.8,2.3, body extent -3.8,-2.3 3.8,2.3, height 3.1
AssemblyNote [mil] "Assembly Note"
DAP0032A_N [mm]
  rrect22% 1.4x0.45 smd: 1(-3.8,4.875) 2(-3.8,4.225) 3(-3.8,3.575) 4(-3.8,2.925) 5(-3.8,2.275) 6(-3.8,1.625) 7(-3.8,0.975) 8(-3.8,0.325) 9(-3.8,-0.325) 10(-3.8,-0.975) 11(-3.8,-1.625) 12(-3.8,-2.275) 13(-3.8,-2.925) 14(-3.8,-3.575) 15(-3.8,-4.225) 16(-3.8,-4.875) 17(3.8,-4.875) 18(3.8,-4.225) 19(3.8,-3.575) 20(3.8,-2.925) 21(3.8,-2.275) 22(3.8,-1.625) 23(3.8,-0.975) 24(3.8,-0.325) 25(3.8,0.325) 26(3.8,0.975) 27(3.8,1.625) 28(3.8,2.275) 29(3.8,2.925) 30(3.8,3.575) 31(3.8,4.225) 32(3.8,4.875)
  rrect2% 5.2x11 smd paste-2.6 mask-2.6: 33(0,0)
  rrect2% 4.11x4.36 on Top Paste: 33(0,0)
  rrect2% 4.11x4.36 on Top Solder: 33(0,0)
  silkscreen extent -4.44,-5.7 3.25,5.7, body extent -4.06,-5.5 4.06,5.5, height 1.2
DBV0005A_N [mm] "SOT23, 5-Leads, Body 2.9x1.6mm, Pitch 0.95mm, Lead Span 2.8mm, IPC Medium Density"
  rrect17% 1x0.6 smd: 1(-1.375,0.95) 2(-1.375,0) 3(-1.375,-0.95) 4(1.375,-0.95) 5(1.375,0.95)
  silkscreen extent -1.63,-1.55 0.38,1.55, body extent -1.42,-1.46 1.42,1.46, height 1.09
DFE252012C [mm] "Toko"
  rect 0.8x2 smd: 1(-1,0) 2(1,0)
  silkscreen extent -1.45,-1.25 1.45,1.25, body extent -1.35,-1.1 1.35,1.1, height 1.2
DQY0008A [mm]
  rrect24% 0.81x0.41 smd mask+0: 1(-2.795,1.905) 2(-2.795,0.635)
  rrect24% 0.81x0.41 smd: 3(-2.795,-0.635) 4(-2.795,-1.905) 5(2.795,-1.905) 6(2.795,-0.635) 8(2.795,1.905)
  rrect24% 0.81x0.41 smd mask+0.102: 7(2.795,0.635)
  rrect3% 3.48x4.46 smd paste-2.217: 9(0,0)
  Top Layer region: -1.25,-2.175 -1,-2.175 -1,-2.7 -1.25,-2.7
  Top Layer region: 1.25,-2.175 1,-2.175 1,-2.7 1.25,-2.7
  Top Layer region: 1.25,2.175 1,2.175 1,2.7 1.25,2.7
  Top Layer region: -1.25,2.175 -1,2.175 -1,2.7 -1.25,2.7
  Top Layer region: -3.25,0.48 -3.25,2.06 -3.237,2.11 -3.2,2.147 -3.15,2.16 -3.15,2.16 -2.44,2.16 -2.402,2.152 -2.369,2.131 -2.348,2.098 -2.34,2.06 -2.34,2.06 -2.34,0.48 -2.348,0.442 -2.369,0.409 -2.402,0.388 -2.44,0.38 -2.44,0.38 -3.15,0.38 -3.188,0.388 -3.221,0.409 -3.242,0.442 -3.25,0.48
  silkscreen extent -3,-2.65 3,2.65, body extent -3.1,-2.6 3.1,2.6, height 1.51
Fairchild_SOD-523F [mm] "SMD, 2-Leads, Body 1.2x0.8mm"
  rect 0.8x0.5 smd: 1(-1,0) 2(1,0)
  silkscreen extent -2.03,-0.65 1.4,0.65, body extent -0.65,-0.45 0.65,0.45, height 0.7
FC_1000x1250 [mm] "TH, 2-Leads, Body 10x12.5mm, Pin Spacing 5mm"
  rect 1.4x1.4 hole 0.9: 1(-2.5,0)
  round 1.4 hole 0.9: 2(2.5,0)
  silkscreen extent -5.25,-5.25 5.25,5.25, body extent -5.25,-5.25 5.25,5.25, height 13.5
HSINK_ATS-TI10P-521-C1-R1 [mil] "HEAT SINK FOR TI MOD,Body 50x13.9mm"
  round 215 hole 115: 1(-787.4,0) 2(787.4,0)
  body extent -984,-281 984,281, height 984
Keystone1502-2 [mm] "Double Turret"
  round 3.5 hole 2.5: 1(0,0)
  silkscreen extent -2.3,-2.3 2.3,2.3, body extent -1.6,-1.6 1.59,1.6, height 5.62
Keystone5003 [mil] "For Keystone 500x miniature loop terminals"
  round 80 hole 40: 1(0,0)
  silkscreen extent -58,-58 58,58, body extent -49,-49 49,49, height 182
Keystone_970 [mm] "PC Mount Phono Jack-White, TH"
  round 2.6 hole 2.08: 1(0,0) 3(9.8,0)
  round 3.4 hole 2.87: 4(8,-5.3)
  round 0 hole 1.98 unplated: M1(0,3.745) M2(0,-3.745)
  round 0 hole 2.08 unplated: M3(6.5,0)
  silkscreen extent -3.99,-5.01 10.03,5.01, body extent -13.33,-5.43 10.03,5.01, height 13.02
Keystone_971 [mm] "PC Mount Phono Jack-Red, TH"
  round 2.6 hole 2.08: 1(0,0) 3(9.8,0)
  round 3.4 hole 2.87: 4(8,-5.3)
  round 0 hole 1.98 unplated: M1(0,3.745) M2(0,-3.745)
  round 0 hole 2.08 unplated: M3(6.5,0)
  silkscreen extent -3.99,-5.01 10.03,5.01, body extent -13.31,-5.44 10.05,5, height 13.02
Keystone_7006 [mm] "KEYSTONE"
  round 8.5 hole 3.658: 1(0,0)
  silkscreen extent -4.8,-4.8 4.8,4.8, body extent -5.68,-5.69 5.7,5.69, height 26.47
Keystone_7007 [mm] "KEYSTONE"
  round 8.5 hole 3.658: 1(0,0)
  silkscreen extent -4.8,-4.8 4.8,4.8, body extent -5.71,-5.66 5.67,5.72, height 26.48
"NY PMS 440 0025 PH" [mm] "4-40 nylon screw and mounting hole"
  round 8 hole 3.2: 1(0,0)
  body extent -3.3,-3.3 3.3,3.3, height 2.69
PBC03SAAN [mm] "Sullins 100mil, 1x3, 230 mil above insulator"
  rect 1.65x1.65 hole 1.016: 1(-2.54,0)
  round 1.65 hole 1.016: 2(0,0) 3(2.54,0)
  silkscreen extent -3.81,-1.27 3.81,1.27, body extent -3.81,-1.27 3.81,1.27, height 8.38
PW0014A_N [mm] "TSOP, 14-Leads, Body 5x4.4mm, Pitch 0.65mm, IPC Medium Density"
  oval 1.4x0.45 smd: 1(-2.95,1.95) 2(-2.95,1.3) 3(-2.95,0.65) 4(-2.95,0) 5(-2.95,-0.65) 6(-2.95,-1.3) 7(-2.95,-1.95) 8(2.95,-1.95) 9(2.95,-1.3) 10(2.95,-0.65) 11(2.95,0) 12(2.95,0.65) 13(2.95,1.3) 14(2.95,1.95)
  silkscreen extent -3.4,-2.55 1.85,2.55, body extent -3.21,-2.5 3.21,2.5, height 1
RTE0016E [mm] "Texas Insturments"
  oval 0.6x0.24 smd paste+0: 1(-1.4,0.75) 2(-1.4,0.25) 3(-1.4,-0.25) 4(-1.4,-0.75) 9(1.4,-0.75) 10(1.4,-0.25) 11(1.4,0.25) 12(1.4,0.75)
  oval 0.24x0.6 smd paste+0: 5(-0.75,-1.4) 6(-0.25,-1.4) 7(0.25,-1.4) 8(0.75,-1.4) 13(0.75,1.4) 14(0.25,1.4) 15(-0.25,1.4) 16(-0.75,1.4)
  rect 0.8x1.2 smd paste-1: 17(0,0)
  silkscreen extent -1.73,-1.73 1.73,1.73, body extent -1.58,-1.58 1.58,1.58, height 0.81
SOT-23 [mm] "SOT23, 3-Leads, Body 2.9x1.3mm, Pitch 0.95mm, Lead Span 2.5mm, IPC Medium Density"
  rrect50% 1x0.6 smd: 1(-1.2,0.95) 2(-1.2,-0.95) 3(1.2,0)
  silkscreen extent -1.62,-1.5 0.7,1.5, body extent -1.16,-1.45 1.21,1.45, height 1
SRT8045 [mil] "SMD, 2-Leads, Body 8x8.4mm"
  round 60 smd: 1(-94.49,0) 2(98.43,0)
  Top Layer region: 157.48,-102.36 102.36,-157.48 35.43,-157.48 35.43,157.48 157.48,157.48
  Top Layer region: -157.48,-102.36 -102.36,-157.48 -35.43,-157.48 -35.43,157.48 -157.48,157.48
  silkscreen extent -169,-177 169,177, body extent -163,-171 163,171, height 181
TSW-102-07-G-S [mm] "Samtec 100mil, 1x2, 230 mil above insulator"
  rrect6% 1.65x1.65 hole 1.016: 1(-1.27,0)
  round 1.65 hole 1.016: 2(1.27,0)
  silkscreen extent -2.54,-1.65 2.54,1.27, body extent -2.54,-1.27 2.54,1.27, height 8.38
TSW-103-07-G-S [mm] "Samtec 100mil, 1x3, 230 mil above insulator"
  rect 1.65x1.65 hole 1.016: 1(-2.54,0)
  round 1.65 hole 1.016: 2(0,0) 3(2.54,0)
  silkscreen extent -3.81,-1.27 3.81,1.65, body extent -3.81,-1.27 3.81,1.27, height 8.38
XAL1350 [mm] "COILCRAFT"
  rect 2.98x12 smd: 1(-4.3,0) 2(4.3,0)
  silkscreen extent -6.6,-7.1 6.6,7.1, body extent -6.6,-7.1 6.6,7.1, height 5.01

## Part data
C1: "CAP, TA, 47 µF, 25 V, +/- 20%, 0.12 ohm, SMD", Cap_Case=D, Manufacturer=Kemet, Supplier Part Number 1=399-4650-1-ND, Tolerance_%=20, Value1="0.12 ohm", Value2=25V, ValueDisplayed=47µF
C2 C6 C7 C8 C9 C25: "CAP, CERM, 22 µF, 25 V, +/- 10%, X5R, 1210", Cap_Case=1210, Manufacturer=MuRata, Supplier Part Number 1=81-GRM32ER61E226KE15, TempCo=X5R, Tolerance_%=10, Value1="0.002 ohm", Value2=25V, ValueDisplayed=22µF
C3 C4 C17 C18 C20 C21: "CAP, CERM, 10 µF, 25 V, +/- 20%, X5R, 0603", Cap_Case=0603, Manufacturer=MuRata, Supplier Part Number 1=490-7202-1-ND, TempCo=X5R, Tolerance_%=20, Value1=Unknown, Value2=25V, ValueDisplayed=10µF
C5 C22: "CAP, CERM, 1 µF, 25 V,+/- 10%, X5R, 0402", Cap_Case=0402, Manufacturer=TDK, Supplier Part Number 1=445-9066-1-ND, TempCo=X5R, Tolerance_%=10, Value2=25V, ValueDisplayed=1µF
C10 C14 C23: "CAP, CERM, 100 pF, 50 V,+/- 5%, C0G/NP0, 0402", Cap_Case=0402, Manufacturer=MuRata, Supplier Part Number 1=81-GRM1555C1H101JA1D, TempCo=C0G/NP0, Tolerance_%=5, Value2=50V, ValueDisplayed=100pF
C11 C12 C15 C16 C19: "CAP, CERM, 0.1 µF, 50 V,+/- 10%, X7R, AEC-Q200 Grade 1, 0402", Cap_Case=0402, Manufacturer=TDK, Supplier Part Number 1=445-6899-1-ND, TempCo=X7R, Tolerance_%=10, Value1="0.039064 ohm", Value2=50V, ValueDisplayed=0.1µF
C13: "CAP, CERM, 0.022 µF, 25 V,+/- 10%, X7R, AEC-Q200 Grade 1, 0402", Cap_Case=0402, Manufacturer=MuRata, Supplier Part Number 1=490-6044-1-ND, TempCo=X7R, Tolerance_%=10, Value2=25V, ValueDisplayed=0.022µF
C26 C27 C31 C38 C41 C42 C43: "CAP, CERM, 1 µF, 25 V, +/- 10%, X5R, 0603", Cap_Case=0603, Manufacturer=MuRata, Supplier Part Number 1=490-3897-1-ND, TempCo=X5R, Tolerance_%=10, Value1=Unknown, Value2=25V, ValueDisplayed=1µF
C29 C34 C35 C36 C37 C55: "CAP, CERM, 0.1 µF, 50 V, +/- 10%, X7R, 0603", Cap_Case=0603, Manufacturer=MuRata, Supplier Part Number 1=490-4779-1-ND, TempCo=X7R, Tolerance_%=10, Value1="0.02 ohm", Value2=50V, ValueDisplayed=0.1µF
C30 C56: "CAP, CERM, 1000 pF, 50 V, +/- 5%, C0G/NP0, 0603", Cap_Case=0603, Manufacturer=MuRata, Supplier Part Number 1=490-1451-1-ND, TempCo=C0G/NP0, Tolerance_%=5, Value1=Unknown, Value2=50V, ValueDisplayed=1000pF
C32 C39 C44 C51: "CAP, CERM, 0.68 µF, 50 V, +/- 10%, X7R, 1206", Cap_Case=1206, Manufacturer=MuRata, Supplier Part Number 1=GRM31MR71H684KA88L-ND, TempCo=X7R, Tolerance_%=10, Value1=Unknown, Value2=50V, ValueDisplayed=0.68µF
C33 C40 C45 C52: "CAP, CERM, 0.01 µF, 50 V, +/- 10%, X7R, 0603", Cap_Case=0603, Manufacturer=MuRata, Supplier Part Number 1=490-1512-1-ND, TempCo=X7R, Tolerance_%=10, Value1=Unknown, Value2=50V, ValueDisplayed=0.01µF
C46: "CAP, CERM, 47 pF, 50 V, +/- 5%, C0G/NP0, 0603", Cap_Case=0603, Manufacturer=MuRata, Supplier Part Number 1=490-1419-1-ND, TempCo=C0G/NP0, Tolerance_%=5, Value1=Unknown, Value2=50V, ValueDisplayed=47pF
C47 C48 C49 C50: "CAP, CERM, 330 pF, 50 V, +/- 5%, C0G/NP0, 0603", Cap_Case=0603, Manufacturer=MuRata, Supplier Part Number 1=490-1439-1-ND, TempCo=C0G/NP0, Tolerance_%=5, Value1=Unknown, Value2=50V, ValueDisplayed=330pF
C53 C54: "CAP, AL, 220 µF, 35 V, +/- 20%, 0.09 ohm, TH", Cap_Case=10x12.5, Manufacturer=Panasonic, Supplier Part Number 1=P10297-ND, Tolerance_%=20, Value1="0.09 ohm", Value2=35V, ValueDisplayed=220µF
D1: "Diode, Zener, 4.3 V, 225 mW, SOT-23", Manufacturer="ON Semiconductor", Power_W=0.225, Supplier Part Number 1=BZX84C4V3LT1GOSCT-ND, Value1=0.225W
D2 D3 D4: "Diode, Switching, 75 V, 0.3 A, SMD, 2-Leads, Body 1.2x0.8mm", Manufacturer="Fairchild Semiconductor", Supplier Part Number 1=1N4148WTCT-ND, Value1=0.3A, Value2=V
H1 H2 H3 H4: "Machine Screw, Round, #4-40 x 1/4, Nylon, Philips panhead", Alternate Manufacturer=-, DigiKeyPartNumber=H542-ND, Manufacturer="B&F Fastener Supply"
H1: "Heatsink FOR TI MOD, 50x13.9mm", Manufacturer="Advanced Thermal Solutions"
J1 J2 J3 J4: library part CMP-0055113-1, "Terminal, Turret, TH, Double", Manufacturer=Keystone, Supplier Part Number 1=36-1502-2-ND
J5 J6 J17: "Header, 100mil, 3x1, Gold, TH", Manufacturer=Samtec, Supplier Part Number 1=SAM1029-03-ND
J7 J8 JP1 JP2 JP3: "Header, 100mil, 2x1, Gold, TH", Color=Black, Current_A=6.3, Manufacturer=Samtec, Supplier Part Number 1=SAM1029-02-ND, Voltage_V=550
J9: library part 971, "RCA Jack, Red, R/A, TH", Manufacturer=Keystone, Supplier Part Number 1=KEY1099-ND
J10: library part 970, "RCA Jack, White, R/A, TH", Manufacturer=Keystone, Supplier Part Number 1=KEY1098-ND
J11 J13: library part 7006, "Binding Post, RED, TH", Manufacturer=Keystone, Shell Color=Red, Supplier Part Number 1=7006K-ND
J12 J14: library part 7007, "Binding Post, BLACK, TH", Manufacturer=Keystone, Shell Color=Black, Supplier Part Number 1=7007K-ND
J15: library part 1502-2, "Terminal, Turret, TH, Double", Manufacturer=Keystone, Supplier Part Number 1=1502-2K-ND
J16: library part PBC03SAAN, "Header, 100mil, 3x1, Gold, TH", Manufacturer="Sullins Connector Solutions", Supplier Part Number 1=S1011E-03-ND
L1: "Inductor, Shielded, Composite, 3 µH, 21 A, 0.0059 ohm, SMD", Manufacturer=Coilcraft, Value1="0.0059 ohm", Value2=21A, ValueDisplayed=3µH
L2: "Inductor, Shielded, Powdered Iron, 2.2 µH, 2.3 A, 0.082 ohm, SMD", Manufacturer="MuRata Toko", PartNumber=DFE252012F-2R2M{}P2, Supplier Part Number 1=490-13055-1-ND, Value1="0.082 ohm", Value2=2.3A, ValueDisplayed=2.2µH
L11 L12 L21 L22: "Inductor, Shielded, Ferrite, 10 µH, 4.2 A, 0.037 ohm, AEC-Q200 Grade 1, SMD", Manufacturer=Coilcraft, Value1="0.037 ohm", Value2=4.2A, ValueDisplayed=10µH
Q1: "MOSFET, 2-CH, N-CH, 30 V, 35 A, DQY0008A (LSON-CLIP-8)", Alternate Manufacturer=None, Manufacturer="Texas Instruments", Supplier Part Number 1=296-28327-6-ND, Value1="0.0088 ohm", Value2="5.9 nC"
Q2 Q4: library part "BC850CLT1G, ON Semiconductor", "Transistor, NPN, 45 V, 0.1 A, SOT-23", Manufacturer="ON Semiconductor", Supplier Part Number 1=BC850CLT1GOSCT-ND, Value1="0.1 A", Value2=800
Q3: "MOSFET, N-CH, 50 V, 0.22 A, SOT-23", Alternate Manufacturer=None, Manufacturer="Fairchild Semiconductor", Supplier Part Number 1=BSS138CT-ND, Value1="6 ohm", Value2="1.7 nC"
R0: "RES, 0.002, 1%, 2 W, 2512", Manufacturer="Stackpole Electronics Inc", Power_W=2, Supplier Part Number 1=CSNL2512FT2L00CT-ND, TempCo="50 ppm/C", Tolerance_%=1, Value1=1%, Value2=2W, Value_Code=2L000, ValueDisplayed=0.002
R01 R02 R5 R6: "RES, 10.0, 1%, 0.063 W, 0402", Manufacturer=Vishay-Dale, Power_W=0.063, Supplier Part Number 1=541-10.0LCT-ND, TempCo="100 ppm/C", Tolerance_%=1, Value1=1%, Value2=0.063W, Value_Code=10R0, ValueDisplayed=10.0
R1: "RES, 49.9, 1%, 0.063 W, 0402", Manufacturer=Vishay-Dale, Power_W=0.063, Supplier Part Number 1=541-49.9LCT-ND, TempCo="100 ppm/C", Tolerance_%=1, Value1=1%, Value2=0.063W, Value_Code=49R9, ValueDisplayed=49.9
R2: "RES, 200 k, 1%, 0.1 W, 0402", Manufacturer=Panasonic, Power_W=0.1, Supplier Part Number 1=P200KLCT-ND, TempCo="100 ppm/C", Tolerance_%=1, Value1=1%, Value2=0.1W, Value_Code=200k
R3: "RES, 56.2 k, 1%, 0.063 W, 0402", Manufacturer=Vishay-Dale, Power_W=0.063, Supplier Part Number 1=541-56.2KLCT-ND, TempCo="100 ppm/C", Tolerance_%=1, Value1=1%, Value2=0.063W, Value_Code=56k2, ValueDisplayed=56.2k
R7: "RES, 7.50 k, 1%, 0.063 W, 0402", Manufacturer=Vishay-Dale, Power_W=0.063, Supplier Part Number 1=541-7.50KLCT-ND, TempCo="100 ppm/C", Tolerance_%=1, Value1=1%, Value2=0.063W, Value_Code=7k50, ValueDisplayed=7.50k
R8: "RES, 137 k, 1%, 0.063 W, 0402", Manufacturer=Vishay-Dale, Power_W=0.063, Supplier Part Number 1=541-137KLCT-ND, TempCo="100 ppm/C", Tolerance_%=1, Value1=1%, Value2=0.063W, Value_Code=137k
R9: "RES, 100 k, 1%, 0.063 W, 0402", Manufacturer=Vishay-Dale, Power_W=0.063, Supplier Part Number 1=541-100KLCT-ND, TempCo="100 ppm/C", Tolerance_%=1, Value1=1%, Value2=0.063W, Value_Code=100k
R10 R11: library part CMP-0081973-1, "RES, 0, 0%, 0.25 W, AEC-Q200 Grade 0, 0603", Manufacturer=Vishay-Dale, Power_W=250mW, Supplier Part Number 1=541-2779-1-ND, Tolerance_%=0%, Value2=0.25W, Value_Code=0
R13 R19 R27 Rg1 Rg2: "RES, 0, 5%, 0.063 W, 0402", Manufacturer=Vishay-Dale, Power_W=0.063, Supplier Part Number 1=541-0.0JCT-ND, TempCo="200 ppm/C", Tolerance_%=5, Value1=5%, Value2=0.063W, Value_Code=0000, ValueDisplayed=0
R14 R18 R20: "RES, 100 k, 0.5%, 0.063 W, 0402", Manufacturer=Vishay-Dale, Power_W=0.063, Supplier Part Number 1=541-100KAVCT-ND, TempCo="50 ppm/C", Tolerance_%=0.5, Value1=0.5%, Value2=0.063W, Value_Code=100k
R15 R16 R21 R22: "RES, 10.2 k, 1%, 0.063 W, 0402", Manufacturer=Vishay-Dale, Power_W=0.063, Supplier Part Number 1=541-10.2KLCT-ND, TempCo="100 ppm/C", Tolerance_%=1, Value1=1%, Value2=0.063W, Value_Code=10k2, ValueDisplayed=10.2k
R17: "RES, 3.01 k, 1%, 0.063 W, 0402", Manufacturer=Vishay-Dale, Power_W=0.063, Supplier Part Number 1=541-3.01KLCT-ND, TempCo="100 ppm/C", Tolerance_%=1, Value1=1%, Value2=0.063W, Value_Code=3k01, ValueDisplayed=3.01k
R23: "RES, 12.1, 1%, 0.063 W, 0402", Manufacturer=Vishay-Dale, Power_W=0.063, Supplier Part Number 1=541-12.1LCT-ND, TempCo="100 ppm/C", Tolerance_%=1, Value1=1%, Value2=0.063W, Value_Code=12R1, ValueDisplayed=12.1
R24: "RES, 1.00 M, 1%, 0.1 W, 0402", Manufacturer=Panasonic, Power_W=0.1, Supplier Part Number 1=P1.00MLCT-ND, TempCo="100 ppm/C", Tolerance_%=1, Value1=1%, Value2=0.1W, Value_Code=1M00, ValueDisplayed=1.00M
R25: "RES, 18.7 k, 1%, 0.063 W, 0402", Manufacturer=Vishay-Dale, Power_W=0.063, Supplier Part Number 1=541-18.7KLCT-ND, TempCo="100 ppm/C", Tolerance_%=1, Value1=1%, Value2=0.063W, Value_Code=18k7, ValueDisplayed=18.7k
R26: "RES, 10.5 k, 1%, 0.1 W, 0603", Manufacturer=Vishay-Dale, Power_W=0.1, Supplier Part Number 1=541-10.5KHCT-ND, TempCo="100 ppm/C", Tolerance_%=1, Value1=1%, Value2=0.1W, Value_Code=10k5, ValueDisplayed=10.5k
R27: "RES, 20.5 k, 1%, 0.063 W, 0402", Manufacturer=Vishay-Dale, Power_W=0.063, Supplier Part Number 1=541-20.5KLCT-ND, TempCo="100 ppm/C", Tolerance_%=1, Value1=1%, Value2=0.063W, Value_Code=20k5, ValueDisplayed=20.5k
R28: "RES, 39 k, 5%, 0.063 W, 0402", Manufacturer=Vishay-Dale, Power_W=0.063, Supplier Part Number 1=541-39KJCT-ND, TempCo="200 ppm/C", Tolerance_%=5, Value1=5%, Value2=0.063W, Value_Code=39k0, ValueDisplayed=39k
R29: "RES, 4.70 k, 0.1%, 0.1 W, 0603", Manufacturer="Susumu Co Ltd", Power_W=0.1, Supplier Part Number 1=RG16P4.7KBCT-ND, TempCo="25 ppm/C", Value1=0.1%, Value2=0.1W, Value_Code=4k70, ValueDisplayed=4.70k
R30 R32 R37 R38 R44: "RES, 100k ohm, 1%, 0.1W, 0603", Manufacturer="Yageo America", Power_W=0.1, Supplier Part Number 1=311-100KHRCT-ND, TempCo="200 ppm/C", Tolerance_%=1, Value1=1%, Value2=0.1W, Value_Code=100k
R31: "RES, 499 k, 1%, 0.1 W, 0603", Manufacturer="Yageo America", Power_W=0.1, Supplier Part Number 1=311-499KHRCT-ND, TempCo="200 ppm/C", Tolerance_%=1, Value1=1%, Value2=0.1W, Value_Code=499k
R33 R34 R35 R36: "RES, 10, 5%, 0.125 W, 0805", Manufacturer=Vishay-Dale, Power_W=0.125, Supplier Part Number 1=541-10ACT-ND, TempCo="200 ppm/C", Tolerance_%=5, Value1=5%, Value2=0.125W, Value_Code=10R0, ValueDisplayed=10
R39 R40 R41 R42: "RES, 3.3, 5%, 0.1 W, 0603", Manufacturer=Vishay-Dale, Power_W=0.1, Supplier Part Number 1=541-3.3GCT-ND, TempCo="200 ppm/C", Tolerance_%=5, Value1=5%, Value2=0.1W, Value_Code=3R30, ValueDisplayed=3.3
R43: "RES, 0, 5%, 0.063 W, 0402", Manufacturer=Panasonic, Power_W=0.063, Supplier Part Number 1=P0.0JCT-ND, TempCo="600 ppm/C", Tolerance_%=5, Value1=5%, Value2=0.063W, Value_Code=0000, ValueDisplayed=0
TP2 TP3 TP5 TP6 TP7: library part 5003, "Test Point, Miniature, Orange, TH", Manufacturer=Keystone, Supplier Part Number 1=36-5003-ND
U1: library part CMP-0067158-1, "Low Iq, Synchronous Boost Controller with Wide Input Voltage and 5.5V Gate Drive for Low Qg  NexFETs, RTE0016E (WQFN-16)", Alternate Manufacturer="Texas Instruments", Alternate PartNumber=TPS43061RTET
U2: "Low-Cost, Low Noise, 5.5 MHz CMOS Operational Amplifier, 2.2 to 5.5 V, -40 to 125 degC, 14-pin SOP (PW0014A), Green (RoHS & no Sb/Br)", Alternate Manufacturer=None, Alternate PartNumber=Equivalent, Manufacturer="Texas Instruments", Supplier Part Number 1=296-28046-5-ND, Total Supply Voltage(Max)(+5V is 5, +/-5V is 10)=5.5, Total Supply Voltage(Min)(+5V is 5, +/-5V is 10)=2.2
U3: library part CMP-0079087-1, "6.5-µA Quiescent Current, 1.8-A Switch Current Boost Converter, DBV0005A (SOT-23-5)", Alternate Manufacturer="Texas Instruments", Alternate PartNumber=TPS613222ADBVT
U4: "2x30-W Class-D Amplifier With Low Idle Power Dissipation, DAP0032A (TSSOP-32)", Alternate Manufacturer="Texas Instruments", Alternate PartNumber=TPA3128D2DAP
ZZ1 ZZ2 ZZ3: library part AssemblyNote, Alternate Manufacturer=-

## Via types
v1: diameter 18, hole 9, Top Layer to Bottom Layer, 291 vias
v2: diameter 22, hole 10, Top Layer to Bottom Layer, 26 vias
v3: diameter 19.68, hole 7.87, Top Layer to Bottom Layer, 18 vias
v4: diameter 19.68, hole 7.87, Top Layer to Bottom Layer, tented both sides, 16 vias
v5: diameter 18, hole 8, Top Layer to Bottom Layer, 9 vias
v6: diameter 40, hole 20, Top Layer to Bottom Layer, 6 vias
v7: diameter 24, hole 12, Top Layer to Bottom Layer, 5 vias
v8: diameter 20, hole 10, Top Layer to Bottom Layer, 2 vias
v9: diameter 30, hole 15, Top Layer to Bottom Layer, 1 vias

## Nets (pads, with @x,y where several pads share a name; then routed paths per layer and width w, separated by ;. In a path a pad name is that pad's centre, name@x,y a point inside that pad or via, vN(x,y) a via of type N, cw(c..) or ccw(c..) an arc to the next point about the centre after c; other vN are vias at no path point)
5V: C4.1 J5.1 U3.4 U3.5 | length 635.4
  Top Layer w25: U3.5@510.86,644.91 U3.4@585.66,644.91 642.89,644.91 C4.1@643.65,645.67 ; J5.1@571.88,1108.92 J5.1@576.68,1104.12 ; J5.1@574.71,1109.13 576.68,1107.15 J5.1@576.68,1104.12 ; C4.1@644.85,642.7 644.85,1035.95 J5.1@576.68,1104.12
\FAULT: R32.2 R37.1 U4.3 | length 231.6
  Top Layer w12: R32.2@3271.55,954.96 3274.72,958.13 R37.1@3340.46,958.13 ; R37.1@3340.19,957.86 R37.1@3340.46,958.13 ; R37.1@3340.57,958.13 R37.1@3340.46,958.13 ; U4.3@3409,1090.66 3409,1047.89 3352.57,991.46 3352.57,970.24 R37.1@3340.46,958.13
\SD: R31.1 U4.2 | length 239
  Top Layer w12: R31.1@3222.89,957.86 3256.73,991.7 3324.44,991.7 3383.4,1050.67 U4.2@3383.4,1090.66
AGND: C3.2 C4.2 C11.2 C12.2 C13.2 C14.2 C15.2 C18.2 C19.2 C22.2 C23.2 D1.1 J6.1 J7.2 J8.2 R3.1 R8.1 R14.1 R15.1 R18.1 R20.1 R21.1 R24.1 R25.1 Rg1.1 Rg2.1 U1.16 U1.17 U2.11 U3.2 U3.3 | length 3386.2
  Top Layer w10: R18.1@1161.65,1029.54 1161.65,1029.22 1162.61,1029.22 1206.6,985.22 1252.51,985.22 1253.47,986.18 1255.49,984.16 U2.11@1255.49,869.61 ; 1211.03,2003.75 1211.03,1996.72 1249.33,1958.43 ; U1.16@1249.33,1979.15 1249.33,1958.43 ; U1.17@1279.16,1920.84 1279.16,1928.59 1249.33,1958.43 ; C11.2@1383.32,1751.56 C11.2@1386.68,1751.56
  Top Layer w12: C3.2@326.55,441.33 591.85,441.33 ; U3.2@548.26,536.65 U3.3@585.66,536.65 590.14,536.65 593.09,539.6 645.12,539.6 645.39,539.86 ; 591.97,441.84 645.89,495.76 C4.2@645.89,580.65 ; D1.1@818.11,897.94 830.74,897.94 943.78,784.9 994.06,784.9 1010.53,768.43 1226.21,768.43 1255.59,797.81 U2.11@1255.59,875.63 ; R8.1@1061.38,2031.75 R8.1@1061.77,2032.15 ; R3.1@1064.75,1812.48 R3.1@1067.98,1809.25 ; C14.2@1064.75,1852.4 C14.2@1066.38,1854.03 ; J7.2@1090,150 1090,174.39 1157.93,242.32 R15.1@1157.93,482.09 ; R15.1@1162.1,482.7 R14.1@1215.81,482.7 ; 1226.21,768.74 1254.96,797.5 U2.11@1254.96,870.41 ; R25.1@1316.45,1031.08 1363.09,1077.72 1501.67,1077.72 1579.26,1000.13 1579.37,1000.13 C23.2@1596.87,982.64 ; R20.1@1355.33,483.2 1406.77,483.2 1407.43,483.86 R21.1@1407.43,481.56 ; R21.1@1405.82,483.17 R21.1@1407.43,481.56 ; J8.2@1520,150 1407.98,262.02 1407.98,481.01 R21.1@1407.43,481.56
  Top Layer w20: C11.2@1383.26,1755.01 1395.09,1755.01 1395.39,1754.71 1459.82,1754.71 Rg1.1@1490.91,1785.8
  Signal Layer 1 w50: J6.1@260.09,1497.08 747.04,1497.08
  other v1: 428.97,309.5 528.97,309.5 628.97,309.5 728.97,309.5 828.97,309.5 528.97,409.5 728.97,409.5 828.97,409.5 240,410 430,410 630,410 628.97,509.5 728.97,509.5 828.97,509.5 1270.19,734.86 1312.98,735.1 1268.94,779.86 1311.73,780.09 896.14,834.44 1483.05,1079.14
  other v3: 1279.16,1907.06 1279.16,1934.62
  other v6: 1029.36,2083.26 1099.05,2083.33
  other v7: 1435.85,1748.27 1529.45,1752.05 1434.45,1782.05 1530,1785 1022.13,1942.46
  other v8: 1190,2020
AVCC: C27.1 J16.2 U4.17 | length 1342
  Top Layer w20: U4.17@3746.46,1370.11 3746.7,1370.35 v2(3774.52,1370.35)
  Top Layer w25: C27.1@4025.43,1313.59 4062.18,1313.59 4063.67,1315.08 v9@4064.57,1315.08
  Signal Layer 1 w25: v9(4064.43,1315.4) 4069.82,1315.4 4123.57,1369.15 4865.36,1369.15 4955.66,1278.85 J16.2@4963.85,1278.85
  Bottom Layer w25: v2@3774.13,1372.62 3775.37,1373.87 4005.96,1373.87 v9(4064.43,1315.4)
AVCC-IN: C25.1 J15.1 J16.1 | length 531.2
  Top Layer w50: C25.1@4828.07,1180.56 4831.5,1180.56 4832.07,1181.13 4833.2,1180 4970,1180 5351.06,1180 J15.1@5356.39,1185.33
Boot: C16.2 U1.11 | length 62.6
  Top Layer w12: U1.11@1334.28,1930.68 1350.96,1930.68 1380.7,1960.41 C16.2@1384.6,1960.41
COMP: C14.1 R7.2 U1.3 | length 217.5
  Top Layer w10: R7.2@1113.62,1950 1139.75,1950 1165.22,1924.53 1165.22,1911.38 ; C14.1@1120.92,1847.68 1121.19,1847.41 1165.22,1891.44 1165.22,1911.38 ; 1164.75,1911.85 1165.22,1911.38 ; U1.3@1224.04,1911 1165.6,1911 1165.22,1911.38
EN: J6.2 R6.2 | length 1601.5
  Top Layer w25: v2@1089.64,2141.5 1151.98,2141.5 R6.2@1153.44,2142.96
  Signal Layer 1 w25: J6.2@260.09,1397.08 234.18,1397.08 182.73,1448.53 182.73,1567.98 213.05,1598.3 570.48,1598.3 ; 580.33,1604.48 664.53,1688.68 664.53,2015.47 725.79,2076.72 726.36,2076.72 789.26,2139.63 v2@1085.86,2139.63
  other v2: 1087.27,2137.98
EN1: C12.1 R6.1 U1.15 | length 197.2
  Top Layer w12: R6.1@1213.97,2141.18 1213.97,2089.89 1216.54,2087.32 ; 1215.43,2089.25 1226.78,2089.25 1254.24,2061.78 1254.24,2019.88 1269.32,2004.81 U1.15@1269.32,1975.96
FB: C23.1 R2.1 R3.2 R26.2 U1.4 | length 1330.1
  Top Layer w10: R2.1@1113.62,1770 1113.62,1803.53 1201.35,1891.25 U1.4@1226,1891.25
  Top Layer w12: v2(1565.08,1058.19) C23.1@1593.41,1029.87 ; C23.1@1593.42,1029.88 R26.2@1646.87,1029.88
  Top Layer w20: R2.1@1114.7,1771.76 1164.41,1771.76 1181.04,1755.13 1181.04,1731.3 1180.91,1731.17 1180.91,1694.81 v2(1177.92,1691.82) ; v2(1208.81,1205.26) 1418.01,1205.26 v2(1565.08,1058.19)
  Signal Layer 1 w20: v2(1177.92,1691.82) 1177.92,1236.14 v2(1208.81,1205.26)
